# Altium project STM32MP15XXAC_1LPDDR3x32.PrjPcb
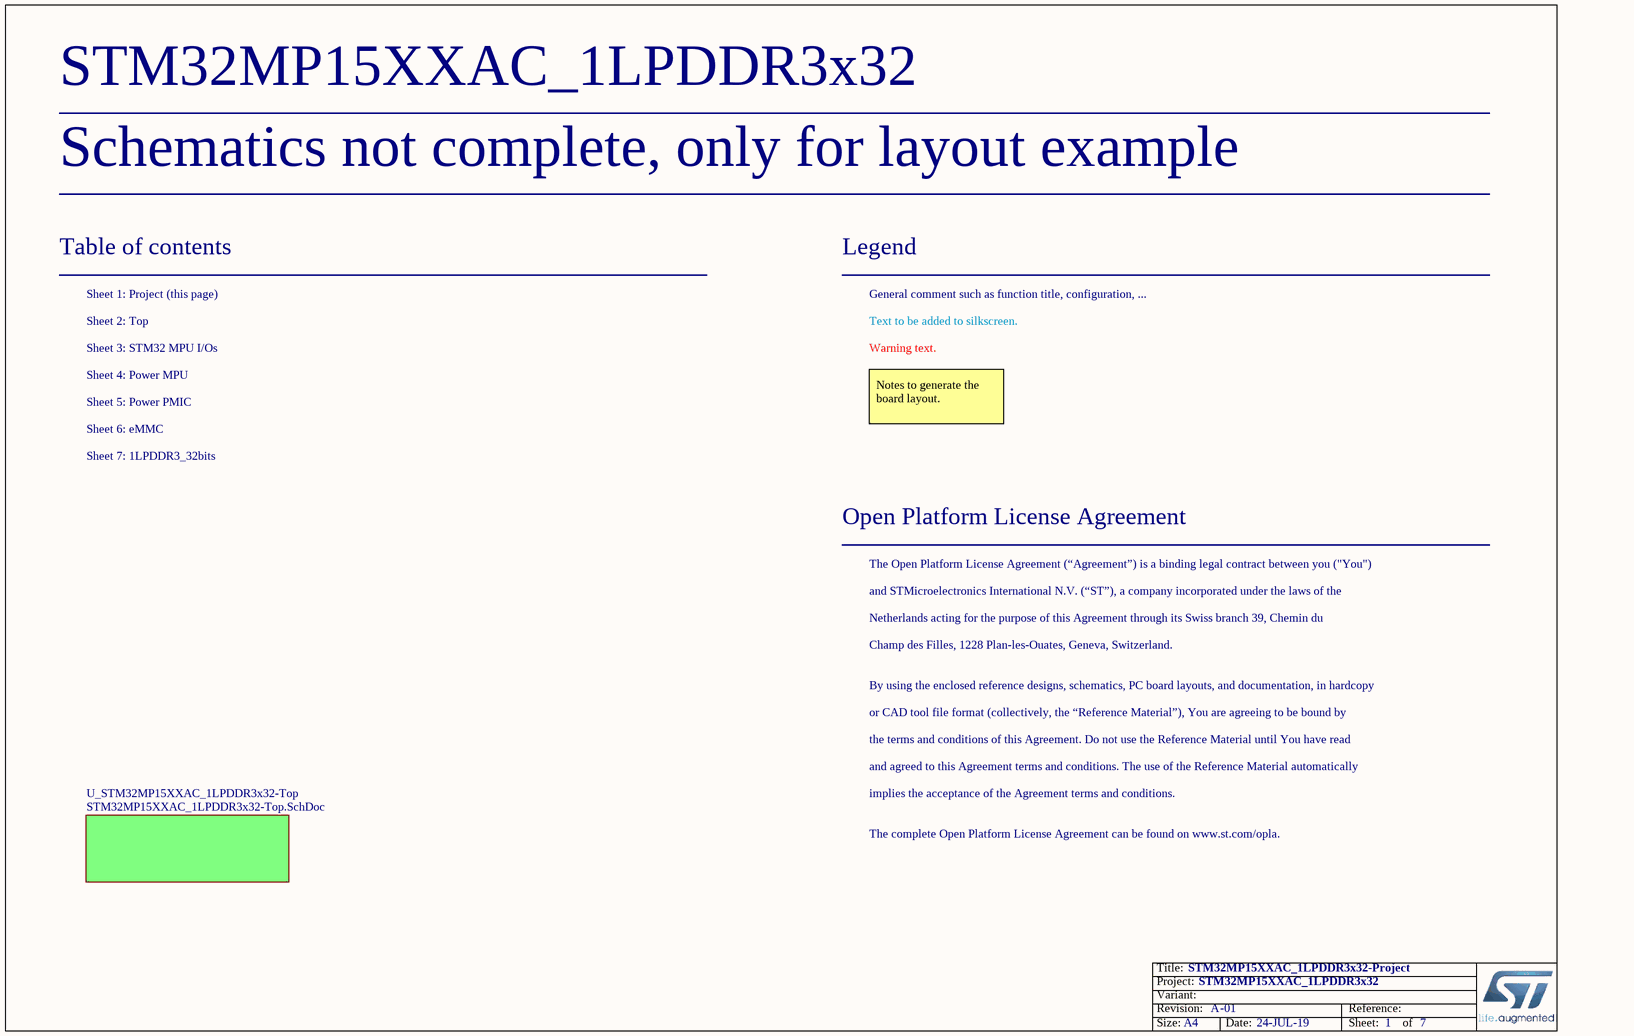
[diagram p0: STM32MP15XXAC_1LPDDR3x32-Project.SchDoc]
Board_Assembly_Revision: 01; Board_Document_Date: 24-JUL-19; Board_Name: STM32MP15XXAC_1LPDDR3x32; Board_PCB_Revision: A
7 sheets, 93 parts. Net scope: flat (ports and power ports of the same name join across sheets).
Board file: STM32MP15XXAC_1LPDDR3x32_A01.PcbDoc
Sheets:
  STM32MP15XXAC_1LPDDR3x32-Project.SchDoc
    U_STM32MP15XXAC_1LPDDR3x32-Top = STM32MP15XXAC_1LPDDR3x32-Top.SchDoc
      U_Power_PMIC = Power_PMIC.SchDoc
      U_Power_MPU = Power_MPU.SchDoc
      U_eMMC = eMMC.SchDoc
      U_STM32_MPU_IOs = STM32_MPU_IOs.SchDoc
      U_1LPDDR3_32bits = 1LPDDR3_32bits.SchDoc

## Sheet STM32MP15XXAC_1LPDDR3x32-Project.SchDoc: STM32MP15XXAC_1LPDDR3x32-Project
size A4; ApprovedBy: Not used; CheckedBy: Not used; Author: Not used; CompanyName: STMicroelectronics; DrawnBy: Not used; Engineer: Not used; Organization: Not used; Address1: Not used; Address2: Not used; Address3: Not used; Address4: Not used; DocumentNumber: Not used; Revision: Not used; SheetNumber: 1; SheetTotal: 7

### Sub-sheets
U_STM32MP15XXAC_1LPDDR3x32-Top = STM32MP15XXAC_1LPDDR3x32-Top.SchDoc: no entries

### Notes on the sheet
- Schematics not complete, only for layout example
- Table of contents
- Sheet 1: Project (this page)
- Legend
- General comment such as function title, configuration, ...
- Sheet 2: Top
- Sheet 3: STM32 MPU I/Os
- Sheet 4: Power MPU
- Text to be added to silkscreen.
- Warning text.
- Sheet 5: Power PMIC
- Sheet 6: eMMC
- Notes to generate the board layout.
- Sheet 7: 1LPDDR3_32bits
- Open Platform License Agreement
- The Open Platform License Agreement (“Agreement”) is a binding legal contract between you ("You")
- and STMicroelectronics International N.V. (“ST”), a company incorporated under the laws of the
- Netherlands acting for the purpose of this Agreement through its Swiss branch 39, Chemin du
- Champ des Filles, 1228 Plan-les-Ouates, Geneva, Switzerland.
- By using the enclosed reference designs, schematics, PC board layouts, and documentation, in hardcopy
- or CAD tool file format (collectively, the “Reference Material”), You are agreeing to be bound by
- the terms and conditions of this Agreement. Do not use the Reference Material until You have read
- and agreed to this Agreement terms and conditions. The use of the Reference Material automatically
- implies the acceptance of the Agreement terms and conditions.
- The complete Open Platform License Agreement can be found on www.st.com/opla.

## Sheet STM32MP15XXAC_1LPDDR3x32-Top.SchDoc: STM32MP15XXAC_1LPDDR3x32-TOP
size A4; Date: Not used; ApprovedBy: Not used; CheckedBy: Not used; Author: Not used; CompanyName: STMicroelectronics; DrawnBy: Not used; Engineer: Not used; Organization: Not used; Address1: Not used; Address2: Not used; Address3: Not used; Address4: Not used; DocumentNumber: Not used; Revision: Not used; SheetNumber: 2; SheetTotal: 7
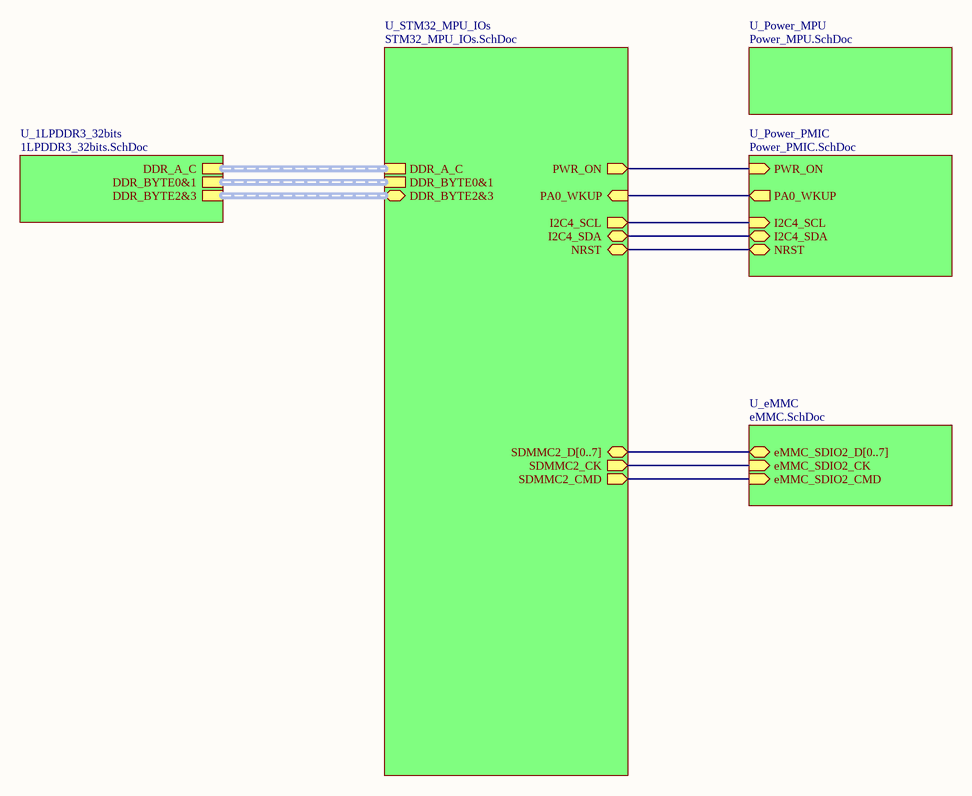
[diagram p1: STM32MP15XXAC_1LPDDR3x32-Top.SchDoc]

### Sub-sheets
U_1LPDDR3_32bits = 1LPDDR3_32bits.SchDoc: DDR_A_C (harness DDR_A_C), DDR_BYTE2&3 (harness DDR_BYTE_2&3), DDR_BYTE0&1 (harness DDR_BYTE_0&1)
U_eMMC = eMMC.SchDoc: eMMC_SDIO2_CK (in), eMMC_SDIO2_D[0..7] (bidir), eMMC_SDIO2_CMD (in)
U_Power_MPU = Power_MPU.SchDoc: no entries
U_Power_PMIC = Power_PMIC.SchDoc: I2C4_SDA (bidir), I2C4_SCL (in), PA0_WKUP (out), NRST (bidir), PWR_ON (in)
U_STM32_MPU_IOs = STM32_MPU_IOs.SchDoc: PA0_WKUP (in), NRST (bidir), PWR_ON (out), I2C4_SCL (out), I2C4_SDA (bidir), DDR_BYTE0&1 (harness DDR_BYTE_0&1), DDR_A_C (harness DDR_A_C), SDMMC2_D[0..7] (bidir), SDMMC2_CMD (out), SDMMC2_CK (out), DDR_BYTE2&3 (harness DDR_BYTE_2&3)

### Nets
(unnamed): sheet U_Power_PMIC/I2C4_SDA, sheet U_STM32_MPU_IOs/I2C4_SDA
(unnamed): sheet U_Power_PMIC/I2C4_SCL, sheet U_STM32_MPU_IOs/I2C4_SCL  [a separate net that carries the same name]
(unnamed): sheet U_Power_PMIC/PA0_WKUP, sheet U_STM32_MPU_IOs/PA0_WKUP  [a separate net that carries the same name]
(unnamed): sheet U_Power_PMIC/NRST, sheet U_STM32_MPU_IOs/NRST  [a separate net that carries the same name]
(unnamed): sheet U_Power_PMIC/PWR_ON, sheet U_STM32_MPU_IOs/PWR_ON  [a separate net that carries the same name]
(unnamed): sheet U_eMMC/eMMC_SDIO2_CK, sheet U_STM32_MPU_IOs/SDMMC2_CK  [a separate net that carries the same name]
(unnamed): sheet U_eMMC/eMMC_SDIO2_CMD, sheet U_STM32_MPU_IOs/SDMMC2_CMD  [a separate net that carries the same name]

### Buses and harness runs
bus sheet U_eMMC/eMMC_SDIO2_D[0..7] = sheet U_STM32_MPU_IOs/SDMMC2_D[0..7]
harness sheet U_1LPDDR3_32bits/DDR_A_C = sheet U_STM32_MPU_IOs/DDR_A_C
harness sheet U_1LPDDR3_32bits/DDR_BYTE0&1 = sheet U_STM32_MPU_IOs/DDR_BYTE0&1
harness sheet U_1LPDDR3_32bits/DDR_BYTE2&3 = sheet U_STM32_MPU_IOs/DDR_BYTE2&3

## Sheet Power_PMIC.SchDoc: Power_PMIC
size A3; CompanyName: STMicroelectronics; Organization: Microcontrollers Division; Address1: 12, Rue Jules HOROWITZ; Address2: 38019 Grenoble; Address3: FRANCE; SheetNumber: 5; SheetTotal: 7
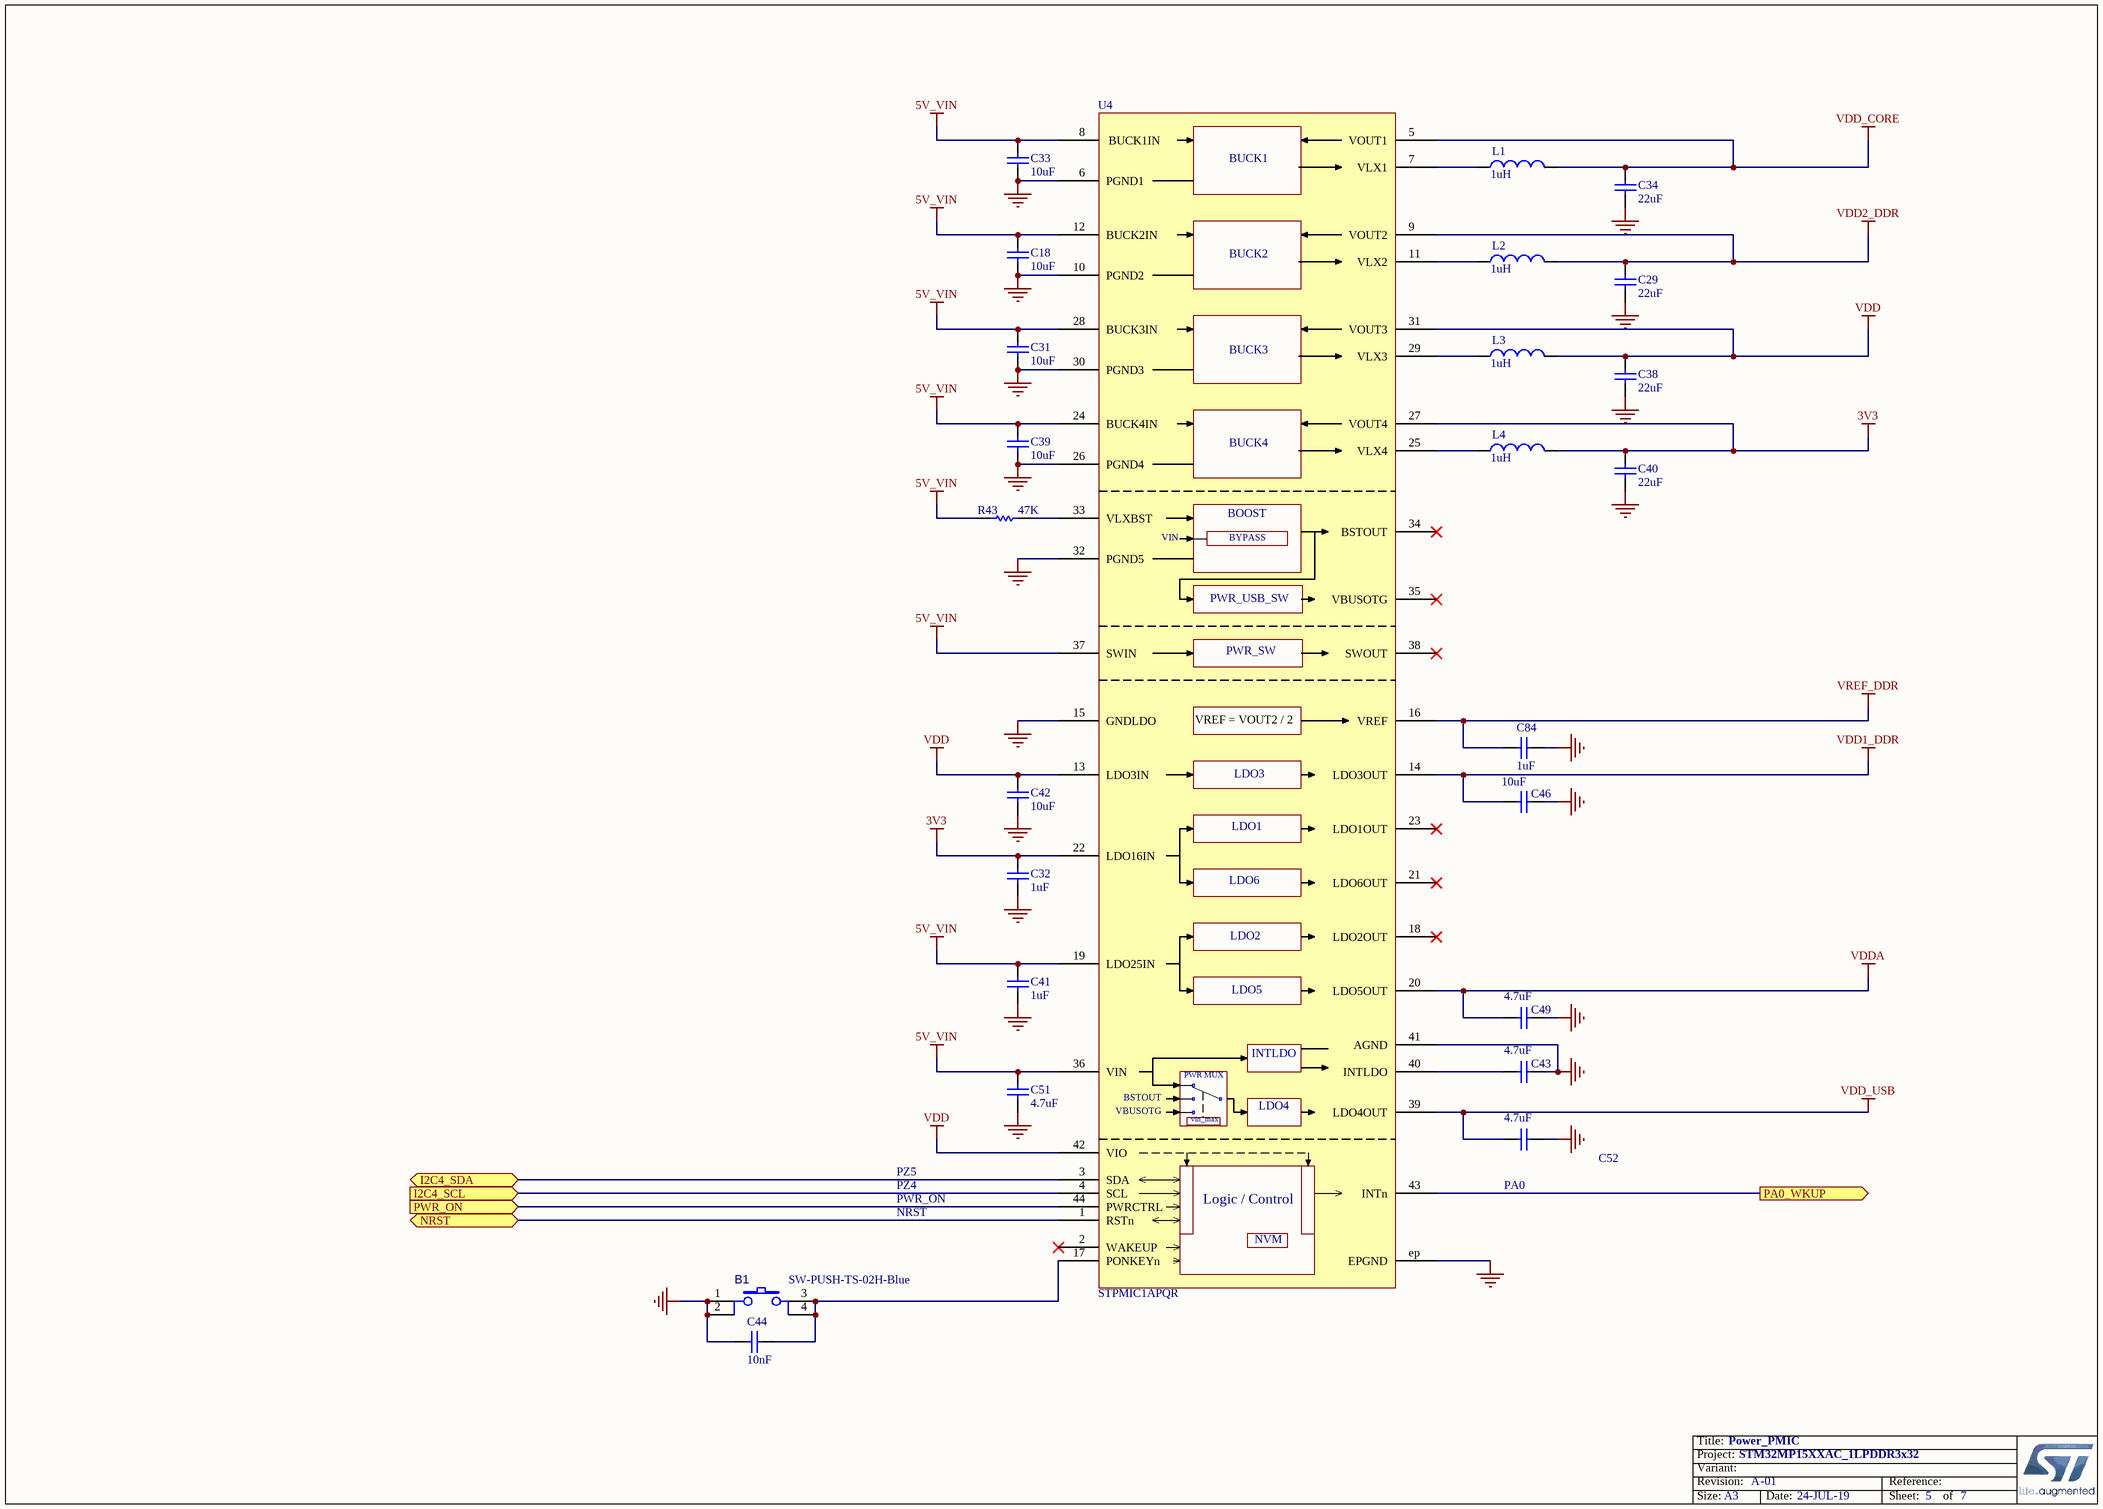
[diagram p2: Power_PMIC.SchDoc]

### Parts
B1  SW-PUSH-TS-02H-Blue  [SWI_JIUBABA_C-TS-02H-2-5-B-V-T_R_BLUE]
C18  value 10uF  [C0603]  (hidden comment: Capacitor)
C29  value 22uF  [C0603]  (hidden comment: Capacitor)
C31  value 10uF  [C0603]  (hidden comment: Capacitor)
C32  value 1uF  [C0402]  (hidden comment: Capacitor)
C33  value 10uF  [C0603]  (hidden comment: Capacitor)
C34  value 22uF  [C0603]  (hidden comment: Capacitor)
C38  value 22uF  [C0603]  (hidden comment: Capacitor)
C39  value 10uF  [C0603]  (hidden comment: Capacitor)
C40  value 22uF  [C0603]  (hidden comment: Capacitor)
C41  value 1uF  [C0402]  (hidden comment: Capacitor)
C42  value 10uF  [C0603]  (hidden comment: Capacitor)
C43  value 4.7uF  [C0402]  (hidden comment: Capacitor)
C44  value 10nF  [C0402]  (hidden comment: Capacitor)
C46  value 10uF  [C0603]  (hidden comment: Capacitor)
C49  value 4.7uF  [C0402]  (hidden comment: Capacitor)
C51  value 4.7uF  [C0402]  (hidden comment: Capacitor)
C52  value 4.7uF  [C0402]  (hidden comment: Capacitor)
C84  value 1uF  [C0402]  (hidden comment: Capacitor)
L1  value 1uH  [IND_2520_TOKO_DFE252012P]  (hidden comment: IND_1uH_42mohm_3.2A)
L2  value 1uH  [IND_2520_TOKO_DFE252012P]  (hidden comment: IND_1uH_42mohm_3.2A)
L3  value 1uH  [IND_2520_TOKO_DFE252012P]  (hidden comment: IND_1uH_42mohm_3.2A)
L4  value 1uH  [IND_2520_TOKO_DFE252012P]  (hidden comment: IND_1uH_42mohm_3.2A)
R43  value 47K  [R0402]  (hidden comment: Resistor)
U4  value STPMIC1APQR  [ICC_WFQFN44-EPAD_5X6_P040]  (hidden comment: STPMU1)

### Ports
I2C4_SCL (in), I2C4_SDA (bidir), NRST (bidir), PA0_WKUP (out), PWR_ON (in)

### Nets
3V3: C32.2 C40.2 L4.2 U4.22(LDO16IN) U4.27(VOUT4)
5V_VIN: C18.2 C31.2 C33.2 C39.2 C41.2 C51.2 R43.2 U4.8(BUCK1IN) U4.12(BUCK2IN) U4.19(LDO25IN) U4.24(BUCK4IN) U4.28(BUCK3IN) U4.36(VIN) U4.37(SWIN)
GND: B1.1 B1.2 C18.1 C29.1 C31.1 C32.1 C33.1 C34.1 C38.1 C39.1 C40.1 C41.1 C42.1 C43.2 C44.1 C46.1 C49.1 C51.1 C52.1 C84.1 U4.6(PGND1) U4.10(PGND2) U4.15(GNDLDO) U4.26(PGND4) U4.30(PGND3) U4.32(PGND5) U4.41(AGND) U4.ep(EPGND)
VDD: C38.2 C42.2 L3.2 U4.13(LDO3IN) U4.31(VOUT3) U4.42(VIO)
VDD1_DDR: C46.2 U4.14(LDO3OUT)
VDD2_DDR: C29.2 L2.2 U4.9(VOUT2)
VDD_CORE: C34.2 L1.2 U4.5(VOUT1)
VDD_USB: C52.2 U4.39(LDO4OUT)
VDDA: C49.2 U4.20(LDO5OUT)
VREF_DDR: C84.2 U4.16(VREF)
I2C4_SCL: U4.4(SCL) ; port I2C4_SCL
I2C4_SDA: U4.3(SDA) ; port I2C4_SDA
NRST: U4.1(RSTn) ; port NRST
PA0_WKUP: U4.43(INTn) ; port PA0_WKUP
PWR_ON: U4.44(PWRCTRL) ; port PWR_ON
NetB1_3: B1.3 B1.4 C44.2 U4.17(PONKEYn)
NetC43_1: C43.1 U4.40(INTLDO)
NetL1_1: L1.1 U4.7(VLX1)
NetL2_1: L2.1 U4.11(VLX2)
NetL3_1: L3.1 U4.29(VLX3)
NetL4_1: L4.1 U4.25(VLX4)
NetR43_1: R43.1 U4.33(VLXBST)

Not connected (* = marked no-connect by the designer): U4 2(WAKEUP)* 18(LDO2OUT)* 21(LDO6OUT)* 23(LDO1OUT)* 34(BSTOUT)* 35(VBUSOTG)* 38(SWOUT)*

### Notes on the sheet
- PZ5
- PZ4
- (near C52) PA0
- NRST
- PWR_ON

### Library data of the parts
B1 = MCD-00172: Switch HW SMD blue; Part_Type: Misc; Manufacturer_Part_Number: C-TS-02H-2.5-B-V-T/R BLUE; Manufacturer: JIUBABA; Provided_By: SUBCO
C18 C31 C33 C39 C42 = MCD-00099: Capacitor, MLCC, 10uF, 10V, X5R, +/-10%, 0603, T=0,8mm; Manufacturer_Part_Number: GRM188R61A106KE69D; Manufacturer: MURATA; Provided_By: SUBCO; ECCN_US: EAR99; ECCN_EU: NEC; Order_Code_RS: 170-6168
C29 C34 C38 C40 = MCD-00100: Capacitor, MLCC, 22uF, 6V3, X5R, +/-20%, 0603, T=0,8mm; Manufacturer_Part_Number: GRM188R60J226MEA0J; Manufacturer: MURATA; Provided_By: SUBCO; ECCN_US: EAR99; ECCN_EU: NEC
C32 C41 C84 = MCD-00095: Capacitor, MLCC, 1uF, 25V, X5R, +/-10%, 0402, T=0,5mm; Manufacturer_Part_Number: GRM155R61E105KA12; Manufacturer: MURATA; Alternate_Manufacturer_Part_Number: GRM155R60J105KE19; Provided_By: SUBCO; ECCN_US: EAR99; ECCN_EU: NEC; Order_Code_RS: 846-7287
C43 C49 C51 C52 = MCD-01356: Capacitor, MLCC, 4.7uF, 6V3, X5R, +/-20%, 0402, T=0,5mm; Manufacturer_Part_Number: GRM155R60J475ME47; Manufacturer: MURATA; Alternate_Manufacturer_Part_Number: GRM155R60J475ME87; ECCN_US: EAR99; ECCN_EU: NEC; Provided_By: SUBCO; Order_Code_RS: 814-5230
C44 = MCD-00011: Capacitor, MLCC, 10nF, 16V, X7R, +/-10%, 0402, T=0.5mm; Manufacturer_Part_Number: CC0402KRX7R7BB103; Manufacturer: YAGEO; Provided_By: SUBCO; ECCN_US: EAR99; ECCN_EU: NEC; Order_Code_RS: 669-8688
C46 = MCD-00099: Capacitor, MLCC, 10uF, 10V, X5R, +/-10%, 0603, T=0,8mm; Manufacturer_Part_Number: GRM188R61A106KE69D; Manufacturer: MURATA; ECCN_US: EAR99; ECCN_EU: NEC; Provided_By: SUBCO; Order_Code_RS: 170-6168
L1-L4 = MCD-01122: Power Inductor ,1uH,4.3A max,+/-20%,0.042ohm,2520; Manufacturer_Part_Number: DFE252012P-1ROM=P2; Manufacturer: MURATA; Provided_By: SUBCO; ECCN_US: EAR99; ECCN_EU: NEC
R43 = MCD-00063: Resistor,47K,0402,1%,1/16W; Manufacturer_Part_Number: RC0402FR-0747KL; Manufacturer: YAGEO; Provided_By: SUBCO; ECCN_US: EAR99; ECCN_EU: NEC
U4 = MCD-01650: ST PMIC:  4 step-down + 1 advanced boost SMPS, 6 LDOs, 2 pwr switches, DDR Vref, NVM option 'A' for IO@3.3V; Part_Type: IC; Manufacturer: STMICROELECTRONICS; BMS_Part_Number: 9177723; ECCN_US: EAR99; ECCN_EU: NEC; Provided_By: SUBCO with ST control; Company_Nationality: Netherlands

## Sheet Power_MPU.SchDoc: Power_MPU
size A3; CompanyName: STMicroelectronics; SheetNumber: 4; SheetTotal: 7
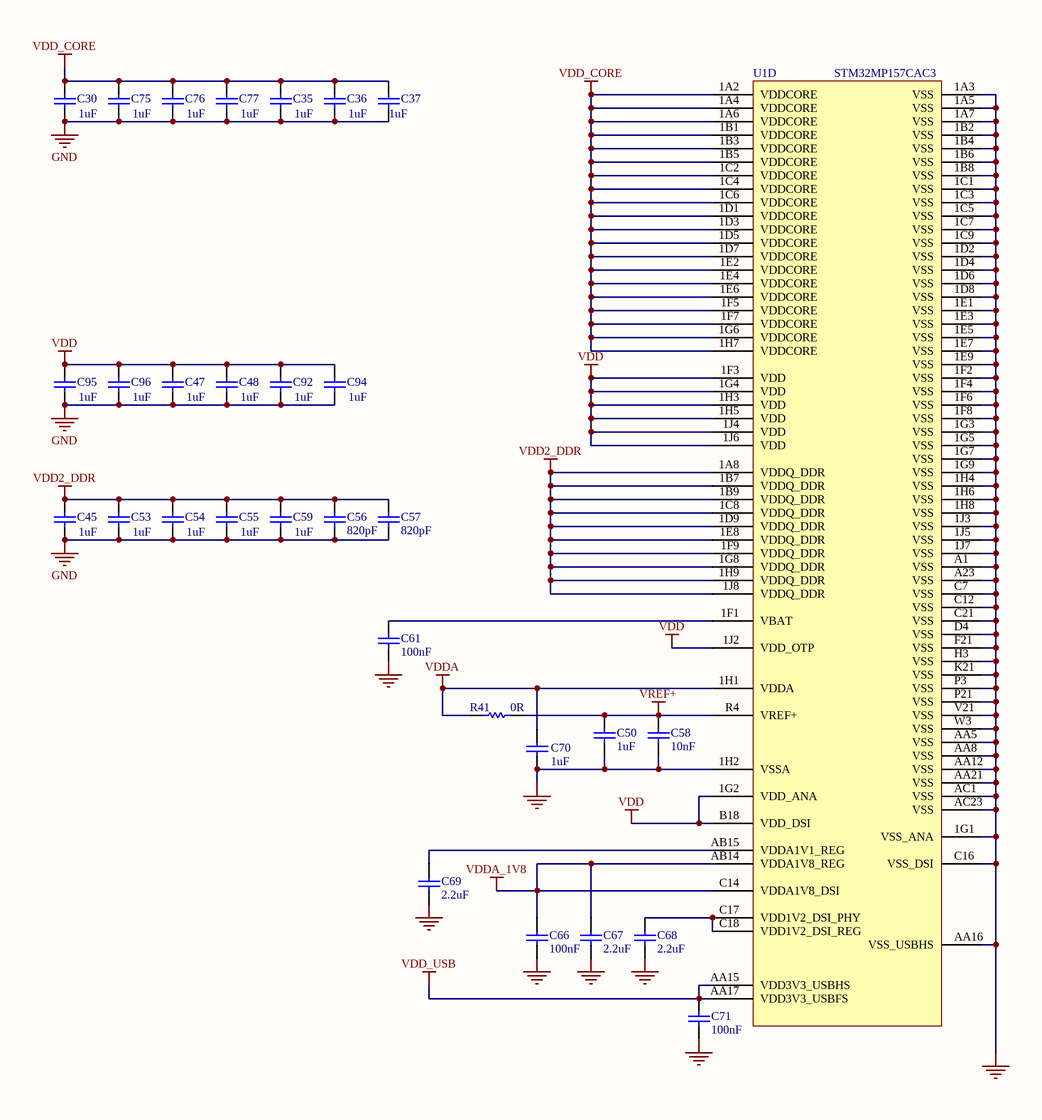
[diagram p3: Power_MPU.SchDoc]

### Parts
C30  value 1uF  [C0402]  (hidden comment: Capacitor)
C35  value 1uF  [C0402]  (hidden comment: Capacitor)
C36  value 1uF  [C0402]  (hidden comment: Capacitor)
C37  value 1uF  [C0402]  (hidden comment: Capacitor)
C45  value 1uF  [C0402]  (hidden comment: Capacitor)
C47  value 1uF  [C0402]  (hidden comment: Capacitor)
C48  value 1uF  [C0402]  (hidden comment: Capacitor)
C50  value 1uF  [C0402]  (hidden comment: Capacitor)
C53  value 1uF  [C0402]  (hidden comment: Capacitor)
C54  value 1uF  [C0402]  (hidden comment: Capacitor)
C55  value 1uF  [C0402]  (hidden comment: Capacitor)
C56  value 820pF  [C0402]  (hidden comment: Capacitor)
C57  value 820pF  [C0402]  (hidden comment: Capacitor)
C58  value 10nF  [C0402]  (hidden comment: Capacitor)
C59  value 1uF  [C0402]  (hidden comment: Capacitor)
C61  value 100nF  [C0402]  (hidden comment: Capacitor)
C66  value 100nF  [C0402]  (hidden comment: Capacitor)
C67  value 2.2uF  [C0402]  (hidden comment: Capacitor)
C68  value 2.2uF  [C0402]  (hidden comment: Capacitor)
C69  value 2.2uF  [C0402]  (hidden comment: Capacitor)
C70  value 1uF  [C0402]  (hidden comment: Capacitor)
C71  value 100nF  [C0402]  (hidden comment: Capacitor)
C75  value 1uF  [C0402]  (hidden comment: Capacitor)
C76  value 1uF  [C0402]  (hidden comment: Capacitor)
C77  value 1uF  [C0402]  (hidden comment: Capacitor)
C92  value 1uF  [C0402]  (hidden comment: Capacitor)
C94  value 1uF  [C0402]  (hidden comment: Capacitor)
C95  value 1uF  [C0402]  (hidden comment: Capacitor)
C96  value 1uF  [C0402]  (hidden comment: Capacitor)
R41  value 0R  [R0402]  (hidden comment: Resistor)
U1  STM32MP157CAC3  [ICC_TFBGA361_12X12_STM32MP157CAC3_P050-065]  (part D of 5)

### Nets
GND: C30.1 C35.1 C36.1 C37.1 C45.1 C47.1 C48.1 C50.1 C53.1 C54.1 C55.1 C56.1 C57.1 C58.1 C59.1 C61.1 C66.1 C67.1 C68.1 C69.1 C70.1 C71.1 C75.1 C76.1 C77.1 C92.1 C94.1 C95.1 C96.1 U1.1A3(VSS) U1.1A5(VSS) U1.1A7(VSS) U1.1B2(VSS) U1.1B4(VSS) U1.1B6(VSS) U1.1B8(VSS) U1.1C1(VSS) U1.1C3(VSS) U1.1C5(VSS) U1.1C7(VSS) U1.1C9(VSS) U1.1D2(VSS) U1.1D4(VSS) U1.1D6(VSS) U1.1D8(VSS) U1.1E1(VSS) U1.1E3(VSS) U1.1E5(VSS) U1.1E7(VSS) U1.1E9(VSS) U1.1F2(VSS) U1.1F4(VSS) U1.1F6(VSS) U1.1F8(VSS) U1.1G1(VSS_ANA) U1.1G3(VSS) U1.1G5(VSS) U1.1G7(VSS) U1.1G9(VSS) U1.1H2(VSSA) U1.1H4(VSS) U1.1H6(VSS) U1.1H8(VSS) U1.1J3(VSS) U1.1J5(VSS) U1.1J7(VSS) U1.A1(VSS) U1.A23(VSS) U1.AA5(VSS) U1.AA8(VSS) U1.AA12(VSS) U1.AA16(VSS_USBHS) U1.AA21(VSS) U1.AC1(VSS) U1.AC23(VSS) U1.C7(VSS) U1.C12(VSS) U1.C16(VSS_DSI) U1.C21(VSS) U1.D4(VSS) U1.F21(VSS) U1.H3(VSS) U1.K21(VSS) U1.P3(VSS) U1.P21(VSS) U1.V21(VSS) U1.W3(VSS)
VDD: C47.2 C48.2 C92.2 C94.2 C95.2 C96.2 U1.1F3(VDD) U1.1G2(VDD_ANA) U1.1G4(VDD) U1.1H3(VDD) U1.1H5(VDD) U1.1J2(VDD_OTP) U1.1J4(VDD) U1.1J6(VDD) U1.B18(VDD_DSI)
VDD2_DDR: C45.2 C53.2 C54.2 C55.2 C56.2 C57.2 C59.2 U1.1A8(VDDQ_DDR) U1.1B7(VDDQ_DDR) U1.1B9(VDDQ_DDR) U1.1C8(VDDQ_DDR) U1.1D9(VDDQ_DDR) U1.1E8(VDDQ_DDR) U1.1F9(VDDQ_DDR) U1.1G8(VDDQ_DDR) U1.1H9(VDDQ_DDR) U1.1J8(VDDQ_DDR)
VDD_CORE: C30.2 C35.2 C36.2 C37.2 C75.2 C76.2 C77.2 U1.1A2(VDDCORE) U1.1A4(VDDCORE) U1.1A6(VDDCORE) U1.1B1(VDDCORE) U1.1B3(VDDCORE) U1.1B5(VDDCORE) U1.1C2(VDDCORE) U1.1C4(VDDCORE) U1.1C6(VDDCORE) U1.1D1(VDDCORE) U1.1D3(VDDCORE) U1.1D5(VDDCORE) U1.1D7(VDDCORE) U1.1E2(VDDCORE) U1.1E4(VDDCORE) U1.1E6(VDDCORE) U1.1F5(VDDCORE) U1.1F7(VDDCORE) U1.1G6(VDDCORE) U1.1H7(VDDCORE)
VDD_USB: C71.2 U1.AA15(VDD3V3_USBHS) U1.AA17(VDD3V3_USBFS)
VDDA: C70.2 R41.1 U1.1H1(VDDA)
VDDA_1V8: C66.2 C67.2 U1.AB14(VDDA1V8_REG) U1.C14(VDDA1V8_DSI)
VREF+: C50.2 C58.2 R41.2 U1.R4(VREF+)
NetC61_2: C61.2 U1.1F1(VBAT)
NetC68_2: C68.2 U1.C17(VDD1V2_DSI_PHY) U1.C18(VDD1V2_DSI_REG)
NetC69_2: C69.2 U1.AB15(VDDA1V1_REG)

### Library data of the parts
C30 C35-C37 C45 C47 C48 C50 C53-C55 C59 C70 C75-C77 C92 C94-C96 = MCD-00095: Capacitor, MLCC, 1uF, 25V, X5R, +/-10%, 0402, T=0,5mm; Manufacturer_Part_Number: GRM155R61E105KA12; Manufacturer: MURATA; Alternate_Manufacturer_Part_Number: GRM155R60J105KE19; ECCN_US: EAR99; ECCN_EU: NEC; Provided_By: SUBCO; Order_Code_RS: 846-7287
C56 C57 = MCD-01508: Capacitor, MLCC, 820pF, 50V, X7R, +/-10%, 0402, T=0.55mm; Manufacturer_Part_Number: CC0402KRX7R9BB821; Manufacturer: YAGEO; ECCN_US: EAR99; ECCN_EU: NEC; Provided_By: SUBCO; Order_Code_RS: 669-8754
C58 = MCD-00011: Capacitor, MLCC, 10nF, 16V, X7R, +/-10%, 0402, T=0.5mm; Manufacturer_Part_Number: CC0402KRX7R7BB103; Manufacturer: YAGEO; ECCN_US: EAR99; ECCN_EU: NEC; Provided_By: SUBCO; Order_Code_RS: 669-8688
C61 C66 C71 = MCD-00006: Capacitor, MLCC, 100nF, 16V, X7R, +/-10%, 0402, T=0.5mm; Manufacturer_Part_Number: CC0402KRX7R7BB104; Manufacturer: YAGEO; Alternate_Manufacturer_Part_Number: GCM155R71C104KA55D; Alternate_Manufacturer: MURATA; ECCN_US: EAR99; ECCN_EU: NEC; Provided_By: SUBCO; Order_Code_RS: 616-9701
C67-C69 = MCD-01823: Capacitor,MLCC, 2.2uF, 6V3, X5R,+/-10%, 0402, T=0.5mm; Manufacturer_Part_Number: GRM155R60J225KE95D; Manufacturer: MURATA; ECCN_US: EAR99; ECCN_EU: NEC; Provided_By: SUBCO; Order_Code_RS: 172-6478
R41 = MCD-00052: Resistor,0R,0402,5%,1/16W; Manufacturer_Part_Number: RC0402JR-070RL; Manufacturer: YAGEO; ECCN_US: EAR99; ECCN_EU: NEC; Provided_By: SUBCO; Order_Code_RS: 618-5804
U1 = MCD-00677: MPU TFBGA12x12 secure boot+crypto; Part_Type: IC; Manufacturer: STMICROELECTRONICS; BMS_Part_Number: 9175503; ECCN_US: 5A002A4; ECCN_EU: NEC; Provided_By: SUBCO with ST control; Company_Nationality: Netherlands

## Sheet eMMC.SchDoc: eMMC
size A3; CompanyName: STMicroelectronics; Address1: 12, Rue Jules HOROWITZ; Address2: 38019 Grenoble; Address3: FRANCE; SheetNumber: 6; SheetTotal: 7
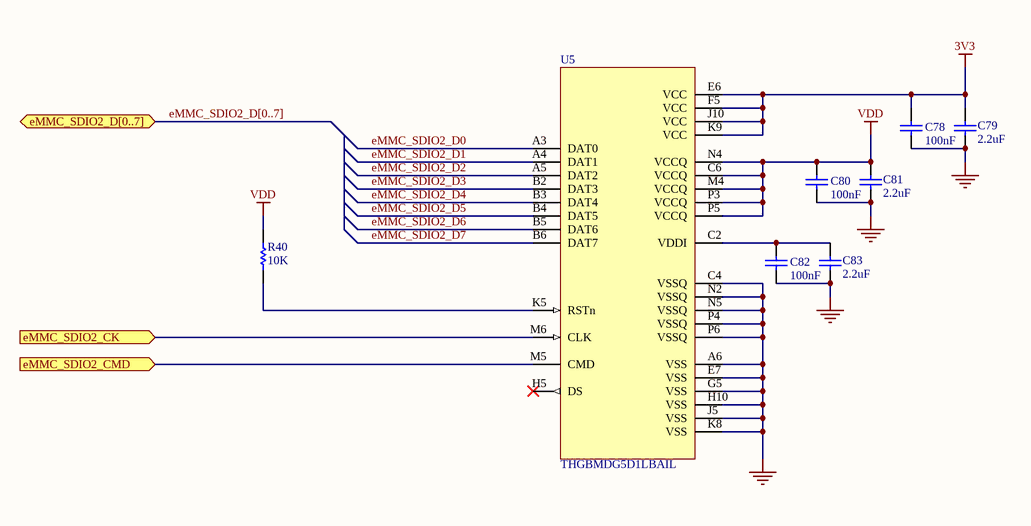
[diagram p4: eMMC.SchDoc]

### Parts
C78  value 100nF  [C0402]  (hidden comment: Capacitor)
C79  value 2.2uF  [C0603]  (hidden comment: Capacitor)
C80  value 100nF  [C0402]  (hidden comment: Capacitor)
C81  value 2.2uF  [C0603]  (hidden comment: Capacitor)
C82  value 100nF  [C0402]  (hidden comment: Capacitor)
C83  value 2.2uF  [C0603]  (hidden comment: Capacitor)
R40  value 10K  [R0402]  (hidden comment: Resistor)
U5  value THGBMDG5D1LBAIL  [ICC_P-WFBGA153_13X11P5_P050]  (hidden comment: eMMC_THGBMDG5D1LBAIL)

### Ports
eMMC_SDIO2_CK (in), eMMC_SDIO2_CMD (in), eMMC_SDIO2_D[0..7] (bidir)

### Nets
3V3: C78.2 C79.2 U5.E6(VCC) U5.F5(VCC) U5.J10(VCC) U5.K9(VCC)
GND: C78.1 C79.1 C80.1 C81.1 C82.1 C83.1 U5.A6(VSS) U5.C4(VSSQ) U5.E7(VSS) U5.G5(VSS) U5.H10(VSS) U5.J5(VSS) U5.K8(VSS) U5.N2(VSSQ) U5.N5(VSSQ) U5.P4(VSSQ) U5.P6(VSSQ)
VDD: C80.2 C81.2 R40.2 U5.C6(VCCQ) U5.M4(VCCQ) U5.N4(VCCQ) U5.P3(VCCQ) U5.P5(VCCQ)
eMMC_SDIO2_CK: U5.M6(CLK) ; port eMMC_SDIO2_CK
eMMC_SDIO2_CMD: U5.M5(CMD) ; port eMMC_SDIO2_CMD
eMMC_SDIO2_D0: U5.A3(DAT0)
eMMC_SDIO2_D1: U5.A4(DAT1)
eMMC_SDIO2_D2: U5.A5(DAT2)
eMMC_SDIO2_D3: U5.B2(DAT3)
eMMC_SDIO2_D4: U5.B3(DAT4)
eMMC_SDIO2_D5: U5.B4(DAT5)
eMMC_SDIO2_D6: U5.B5(DAT6)
eMMC_SDIO2_D7: U5.B6(DAT7)
NetC82_2: C82.2 C83.2 U5.C2(VDDI)
NetR40_1: R40.1 U5.K5(RSTn)

Not connected (* = marked no-connect by the designer): U5 H5(DS)*

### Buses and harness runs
bus eMMC_SDIO2_D[0..7] = port eMMC_SDIO2_D[0..7]

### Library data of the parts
C78 C80 C82 = MCD-00006: Capacitor, MLCC, 100nF, 16V, X7R, +/-10%, 0402, T=0.5mm; Manufacturer_Part_Number: CC0402KRX7R7BB104; Manufacturer: YAGEO; Alternate_Manufacturer_Part_Number: GCM155R71C104KA55D; Alternate_Manufacturer: MURATA; Provided_By: SUBCO; ECCN_US: EAR99; ECCN_EU: NEC; Order_Code_RS: 616-9701
C79 C81 C83 = MCD-00012: Capacitor, MLCC, 2.2uF, 10V, X5R, +/- 10%, 0603, T=0,8mm; Manufacturer_Part_Number: CC0603KRX5R6BB225; Manufacturer: YAGEO; Alternate_Manufacturer_Part_Number: C0603C225K8PACTU; Alternate_Manufacturer: KEMET; BMS_Part_Number: 9142010; Provided_By: SUBCO; ECCN_US: EAR99; ECCN_EU: NEC
R40 = MCD-00053: Resistor,10K,0402,1%,1/16W; Manufacturer_Part_Number: RC0402FR-0710KL; Manufacturer: YAGEO; BMS_Part_Number: 9131590; Provided_By: SUBCO; ECCN_US: EAR99; ECCN_EU: NEC
U5 = MCD-00110: Memory,e-MMC,4GB,3V3,WFBGA,153pins; Part_Type: IC; Manufacturer: TOSHIBA; BMS_Part_Number: 9171005; Provided_By: SUBCO; ECCN_US: 3A991; ECCN_EU: NEC

## Sheet STM32_MPU_IOs.SchDoc: MPU
size A3; SheetNumber: 3; SheetTotal: 7
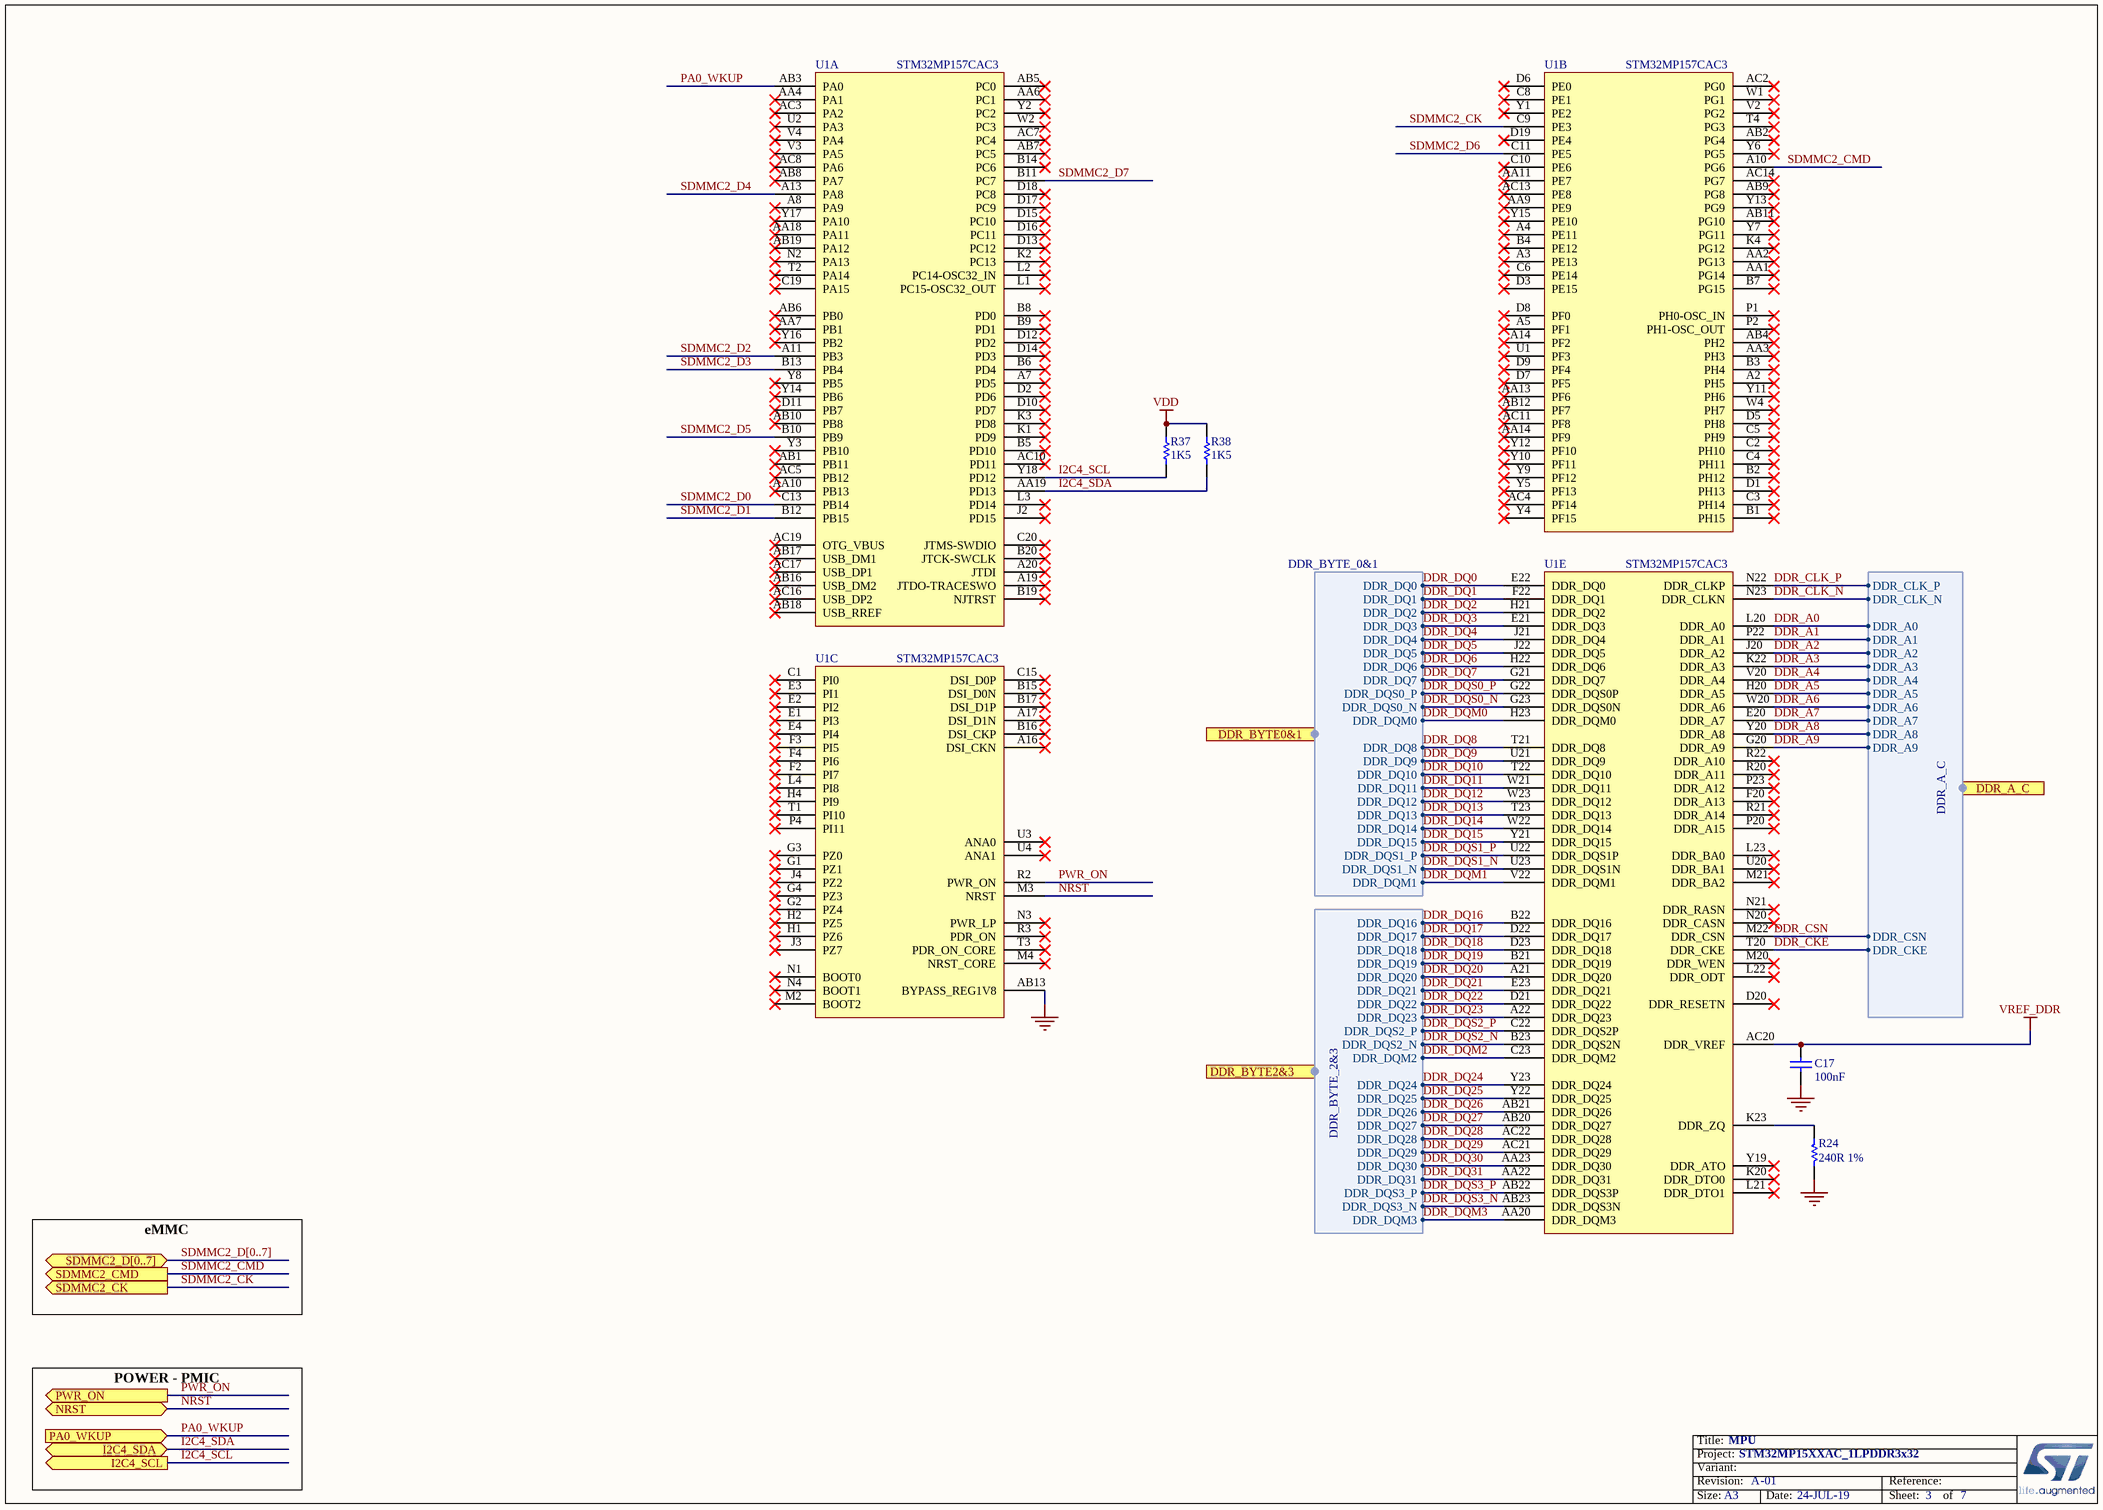
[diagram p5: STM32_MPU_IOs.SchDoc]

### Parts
C17  value 100nF  [C0402]  (hidden comment: Capacitor)
R24  value 240R 1%  [R0402]  (hidden comment: Resistor)
R37  value 1K5  [R0402]  (hidden comment: Resistor)
R38  value 1K5  [R0402]  (hidden comment: Resistor)
U1  STM32MP157CAC3  [ICC_TFBGA361_12X12_STM32MP157CAC3_P050-065]  (parts A,B,C,E of 5)

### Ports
DDR_A_C (harness DDR_A_C), DDR_BYTE0&1 (harness DDR_BYTE_0&1), DDR_BYTE2&3 (harness DDR_BYTE_2&3), I2C4_SCL (out), I2C4_SDA (bidir), NRST (bidir), PA0_WKUP (in), PWR_ON (out), SDMMC2_CK (out), SDMMC2_CMD (out), SDMMC2_D[0..7] (bidir)

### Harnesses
DDR_BYTE_0&1: DDR_DQ0, DDR_DQ1, DDR_DQ2, DDR_DQ3, DDR_DQ4, DDR_DQ5, DDR_DQ6, DDR_DQ7, DDR_DQS0_P, DDR_DQS0_N, DDR_DQM0, DDR_DQ8, DDR_DQ9, DDR_DQ10, DDR_DQ11, DDR_DQ12, DDR_DQ13, DDR_DQ14, DDR_DQ15, DDR_DQS1_P, DDR_DQS1_N, DDR_DQM1
DDR_BYTE_2&3: DDR_DQ20, DDR_DQ16, DDR_DQ18, DDR_DQ17, DDR_DQ22, DDR_DQ19, DDR_DQ21, DDR_DQ23, DDR_DQS2_P, DDR_DQS2_N, DDR_DQ26, DDR_DQM2, DDR_DQ24, DDR_DQ28, DDR_DQ25, DDR_DQ27, DDR_DQ29, DDR_DQ30, DDR_DQ31, DDR_DQS3_P, DDR_DQS3_N, DDR_DQM3
DDR_A_C: DDR_CLK_P, DDR_CLK_N, DDR_A0, DDR_A1, DDR_A2, DDR_A3, DDR_A4, DDR_A5, DDR_A6, DDR_A7, DDR_A8, DDR_A9, DDR_CSN, DDR_CKE

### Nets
GND: C17.2 R24.2 U1.AB13(BYPASS_REG1V8)
VDD: R37.1 R38.1
VREF_DDR: C17.1 U1.AC20(DDR_VREF)
DDR_A0: U1.L20(DDR_A0) ; port DDR_A_C.DDR_A0
DDR_A1: U1.P22(DDR_A1) ; port DDR_A_C.DDR_A1
DDR_A2: U1.J20(DDR_A2) ; port DDR_A_C.DDR_A2
DDR_A3: U1.K22(DDR_A3) ; port DDR_A_C.DDR_A3
DDR_A4: U1.V20(DDR_A4) ; port DDR_A_C.DDR_A4
DDR_A5: U1.H20(DDR_A5) ; port DDR_A_C.DDR_A5
DDR_A6: U1.W20(DDR_A6) ; port DDR_A_C.DDR_A6
DDR_A7: U1.E20(DDR_A7) ; port DDR_A_C.DDR_A7
DDR_A8: U1.Y20(DDR_A8) ; port DDR_A_C.DDR_A8
DDR_A9: U1.G20(DDR_A9) ; port DDR_A_C.DDR_A9
DDR_CKE: U1.T20(DDR_CKE) ; port DDR_A_C.DDR_CKE
DDR_CLK_N: U1.N23(DDR_CLKN) ; port DDR_A_C.DDR_CLK_N
DDR_CLK_P: U1.N22(DDR_CLKP) ; port DDR_A_C.DDR_CLK_P
DDR_CSN: U1.M22(DDR_CSN) ; port DDR_A_C.DDR_CSN
DDR_DQ0: U1.E22(DDR_DQ0) ; port DDR_BYTE0&1.DDR_DQ0
DDR_DQ1: U1.F22(DDR_DQ1) ; port DDR_BYTE0&1.DDR_DQ1
DDR_DQ2: U1.H21(DDR_DQ2) ; port DDR_BYTE0&1.DDR_DQ2
DDR_DQ3: U1.E21(DDR_DQ3) ; port DDR_BYTE0&1.DDR_DQ3
DDR_DQ4: U1.J21(DDR_DQ4) ; port DDR_BYTE0&1.DDR_DQ4
DDR_DQ5: U1.J22(DDR_DQ5) ; port DDR_BYTE0&1.DDR_DQ5
DDR_DQ6: U1.H22(DDR_DQ6) ; port DDR_BYTE0&1.DDR_DQ6
DDR_DQ7: U1.G21(DDR_DQ7) ; port DDR_BYTE0&1.DDR_DQ7
DDR_DQ8: U1.T21(DDR_DQ8) ; port DDR_BYTE0&1.DDR_DQ8
DDR_DQ9: U1.U21(DDR_DQ9) ; port DDR_BYTE0&1.DDR_DQ9
DDR_DQ10: U1.T22(DDR_DQ10) ; port DDR_BYTE0&1.DDR_DQ10
DDR_DQ11: U1.W21(DDR_DQ11) ; port DDR_BYTE0&1.DDR_DQ11
DDR_DQ12: U1.W23(DDR_DQ12) ; port DDR_BYTE0&1.DDR_DQ12
DDR_DQ13: U1.T23(DDR_DQ13) ; port DDR_BYTE0&1.DDR_DQ13
DDR_DQ14: U1.W22(DDR_DQ14) ; port DDR_BYTE0&1.DDR_DQ14
DDR_DQ15: U1.Y21(DDR_DQ15) ; port DDR_BYTE0&1.DDR_DQ15
DDR_DQ16: U1.B22(DDR_DQ16) ; port DDR_BYTE2&3.DDR_DQ16
DDR_DQ17: U1.D22(DDR_DQ17) ; port DDR_BYTE2&3.DDR_DQ17
DDR_DQ18: U1.D23(DDR_DQ18) ; port DDR_BYTE2&3.DDR_DQ18
DDR_DQ19: U1.B21(DDR_DQ19) ; port DDR_BYTE2&3.DDR_DQ19
DDR_DQ20: U1.A21(DDR_DQ20) ; port DDR_BYTE2&3.DDR_DQ20
DDR_DQ21: U1.E23(DDR_DQ21) ; port DDR_BYTE2&3.DDR_DQ21
DDR_DQ22: U1.D21(DDR_DQ22) ; port DDR_BYTE2&3.DDR_DQ22
DDR_DQ23: U1.A22(DDR_DQ23) ; port DDR_BYTE2&3.DDR_DQ23
DDR_DQ24: U1.Y23(DDR_DQ24) ; port DDR_BYTE2&3.DDR_DQ24
DDR_DQ25: U1.Y22(DDR_DQ25) ; port DDR_BYTE2&3.DDR_DQ25
DDR_DQ26: U1.AB21(DDR_DQ26) ; port DDR_BYTE2&3.DDR_DQ26
DDR_DQ27: U1.AB20(DDR_DQ27) ; port DDR_BYTE2&3.DDR_DQ27
DDR_DQ28: U1.AC22(DDR_DQ28) ; port DDR_BYTE2&3.DDR_DQ28
DDR_DQ29: U1.AC21(DDR_DQ29) ; port DDR_BYTE2&3.DDR_DQ29
DDR_DQ30: U1.AA23(DDR_DQ30) ; port DDR_BYTE2&3.DDR_DQ30
DDR_DQ31: U1.AA22(DDR_DQ31) ; port DDR_BYTE2&3.DDR_DQ31
DDR_DQM0: U1.H23(DDR_DQM0) ; port DDR_BYTE0&1.DDR_DQM0
DDR_DQM1: U1.V22(DDR_DQM1) ; port DDR_BYTE0&1.DDR_DQM1
DDR_DQM2: U1.C23(DDR_DQM2) ; port DDR_BYTE2&3.DDR_DQM2
DDR_DQM3: U1.AA20(DDR_DQM3) ; port DDR_BYTE2&3.DDR_DQM3
DDR_DQS0_N: U1.G23(DDR_DQS0N) ; port DDR_BYTE0&1.DDR_DQS0_N
DDR_DQS0_P: U1.G22(DDR_DQS0P) ; port DDR_BYTE0&1.DDR_DQS0_P
DDR_DQS1_N: U1.U23(DDR_DQS1N) ; port DDR_BYTE0&1.DDR_DQS1_N
DDR_DQS1_P: U1.U22(DDR_DQS1P) ; port DDR_BYTE0&1.DDR_DQS1_P
DDR_DQS2_N: U1.B23(DDR_DQS2N) ; port DDR_BYTE2&3.DDR_DQS2_N
DDR_DQS2_P: U1.C22(DDR_DQS2P) ; port DDR_BYTE2&3.DDR_DQS2_P
DDR_DQS3_N: U1.AB23(DDR_DQS3N) ; port DDR_BYTE2&3.DDR_DQS3_N
DDR_DQS3_P: U1.AB22(DDR_DQS3P) ; port DDR_BYTE2&3.DDR_DQS3_P
I2C4_SCL: R37.2 U1.Y18(PD12) ; port I2C4_SCL
I2C4_SDA: R38.2 U1.AA19(PD13) ; port I2C4_SDA
NRST: U1.M3(NRST) ; port NRST
PA0_WKUP: U1.AB3(PA0) ; port PA0_WKUP
PWR_ON: U1.R2(PWR_ON) ; port PWR_ON
SDMMC2_CK: U1.C9(PE3) ; port SDMMC2_CK
SDMMC2_CMD: U1.A10(PG6) ; port SDMMC2_CMD
SDMMC2_D0: U1.C13(PB14)
SDMMC2_D1: U1.B12(PB15)
SDMMC2_D2: U1.A11(PB3)
SDMMC2_D3: U1.B13(PB4)
SDMMC2_D4: U1.A13(PA8)
SDMMC2_D5: U1.B10(PB9)
SDMMC2_D6: U1.C11(PE5)
SDMMC2_D7: U1.B11(PC7)
NetR24_1: R24.1 U1.K23(DDR_ZQ)

Not connected (* = marked no-connect by the designer): U1 A2(PH5)* A3(PE13)* A4(PE11)* A5(PF1)* A7(PD5)* A8(PA9)* A14(PF2)* A16(DSI_CKN)* A17(DSI_D1N)* A19(JTDO-TRACESWO)* A20(JTDI)* AA1(PG14)* AA2(PG13)* AA3(PH3)* AA4(PA1)* AA6(PC1)* AA7(PB1)* AA9(PE9)* AA10(PB13)* AA11(PE7)* AA13(PF6)* AA14(PF9)* AA18(PA11)* AB1(PB11)* AB2(PG4)* AB4(PH2)* AB5(PC0)* AB6(PB0)* AB7(PC5)* AB8(PA7)* AB9(PG8)* AB10(PB8)* AB11(PG10)* AB12(PF7)* AB16(USB_DM2)* AB17(USB_DM1)* AB18(USB_RREF)* AB19(PA12)* AC2(PG0)* AC3(PA2)* AC4(PF14)* AC5(PB12)* AC7(PC4)* AC8(PA6)* AC10(PD11)* AC11(PF8)* AC13(PE8)* AC14(PG7)* AC16(USB_DP2)* AC17(USB_DP1)* AC19(OTG_VBUS)* B1(PH15)* B2(PH12)* B3(PH4)* B4(PE12)* B5(PD10)* B6(PD4)* B7(PG15)* B8(PD0)* B9(PD1)* B14(PC6)* B15(DSI_D0N)* B16(DSI_CKP)* B17(DSI_D1P)* B19(NJTRST)* B20(JTCK-SWCLK)* C1(PI0)* C2(PH10)* C3(PH14)* C4(PH11)* C5(PH9)* C6(PE14)* C8(PE1)* C10(PE6)* C15(DSI_D0P)* C19(PA15)* C20(JTMS-SWDIO)* D1(PH13)* D2(PD6)* D3(PE15)* D5(PH8)* D6(PE0)* D7(PF5)* D8(PF0)* D9(PF4)* D10(PD7)* D11(PB7)* D12(PD2)* D13(PC12)* D14(PD3)* D15(PC10)* D16(PC11)* D17(PC9)* D18(PC8)* D19(PE4)* D20(DDR_RESETN)* E1(PI3)* E2(PI2)* E3(PI1)* E4(PI4)* F2(PI7)* F3(PI5)* F4(PI6)* F20(DDR_A13)* G1(PZ1)* G2(PZ4)* G3(PZ0)* G4(PZ3)* H1(PZ6)* H2(PZ5)* H4(PI9)* J2(PD15)* J3(PZ7)* J4(PZ2)* K1(PD9)* K2(PC13)* K3(PD8)* K4(PG12)* K20(DDR_DTO0)* L1(PC15-OSC32_OUT)* L2(PC14-OSC32_IN)* L3(PD14)* L4(PI8)* L21(DDR_DTO1)* L22(DDR_ODT)* L23(DDR_BA0)* M2(BOOT2)* M4(NRST_CORE)* M20(DDR_WEN)* M21(DDR_BA2)* N1(BOOT0)* N2(PA13)* N3(PWR_LP)* N4(BOOT1)* N20(DDR_CASN)* N21(DDR_RASN)* P1(PH0-OSC_IN)* P2(PH1-OSC_OUT)* P4(PI11)* P20(DDR_A15)* P23(DDR_A12)* R3(PDR_ON)* R20(DDR_A11)* R21(DDR_A14)* R22(DDR_A10)* T1(PI10)* T2(PA14)* T3(PDR_ON_CORE)* T4(PG3)* U1(PF3)* U2(PA3)* U3(ANA0)* U4(ANA1)* U20(DDR_BA1)* V2(PG2)* V3(PA5)* V4(PA4)* W1(PG1)* W2(PC3)* W4(PH7)* Y1(PE2)* Y2(PC2)* Y3(PB10)* Y4(PF15)* Y5(PF13)* Y6(PG5)* Y7(PG11)* Y8(PB5)* Y9(PF12)* Y10(PF11)* Y11(PH6)* Y12(PF10)* Y13(PG9)* Y14(PB6)* Y15(PE10)* Y16(PB2)* Y17(PA10)* Y19(DDR_ATO)*

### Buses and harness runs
bus SDMMC2_D[0..7] = port SDMMC2_D[0..7]

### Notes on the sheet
- eMMC
- POWER - PMIC

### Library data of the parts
C17 = MCD-00006: as C78 on sheet eMMC
R24 = MCD-00120: Resistor,240R,0402,1%,1/16W; Manufacturer_Part_Number: RC0402FR-07240RL; Manufacturer: YAGEO; ECCN_US: EAR99; ECCN_EU: NEC; Provided_By: SUBCO
R37 R38 = MCD-00068: Resistor,1K5,0402,1%,1/16W; Manufacturer_Part_Number: RC0402FR-071K5L; Manufacturer: YAGEO; ECCN_US: EAR99; ECCN_EU: NEC; Provided_By: SUBCO
U1 = MCD-00677: as U1 on sheet Power_MPU

## Sheet 1LPDDR3_32bits.SchDoc: 1LPDDR3 32 Bits
size A3; CompanyName: STMicroelectronics; Address1: 12, Rue Jules HOROWITZ; Address2: 38019 Grenoble; Address3: FRANCE; DocumentNumber: .; SheetNumber: 7; SheetTotal: 7
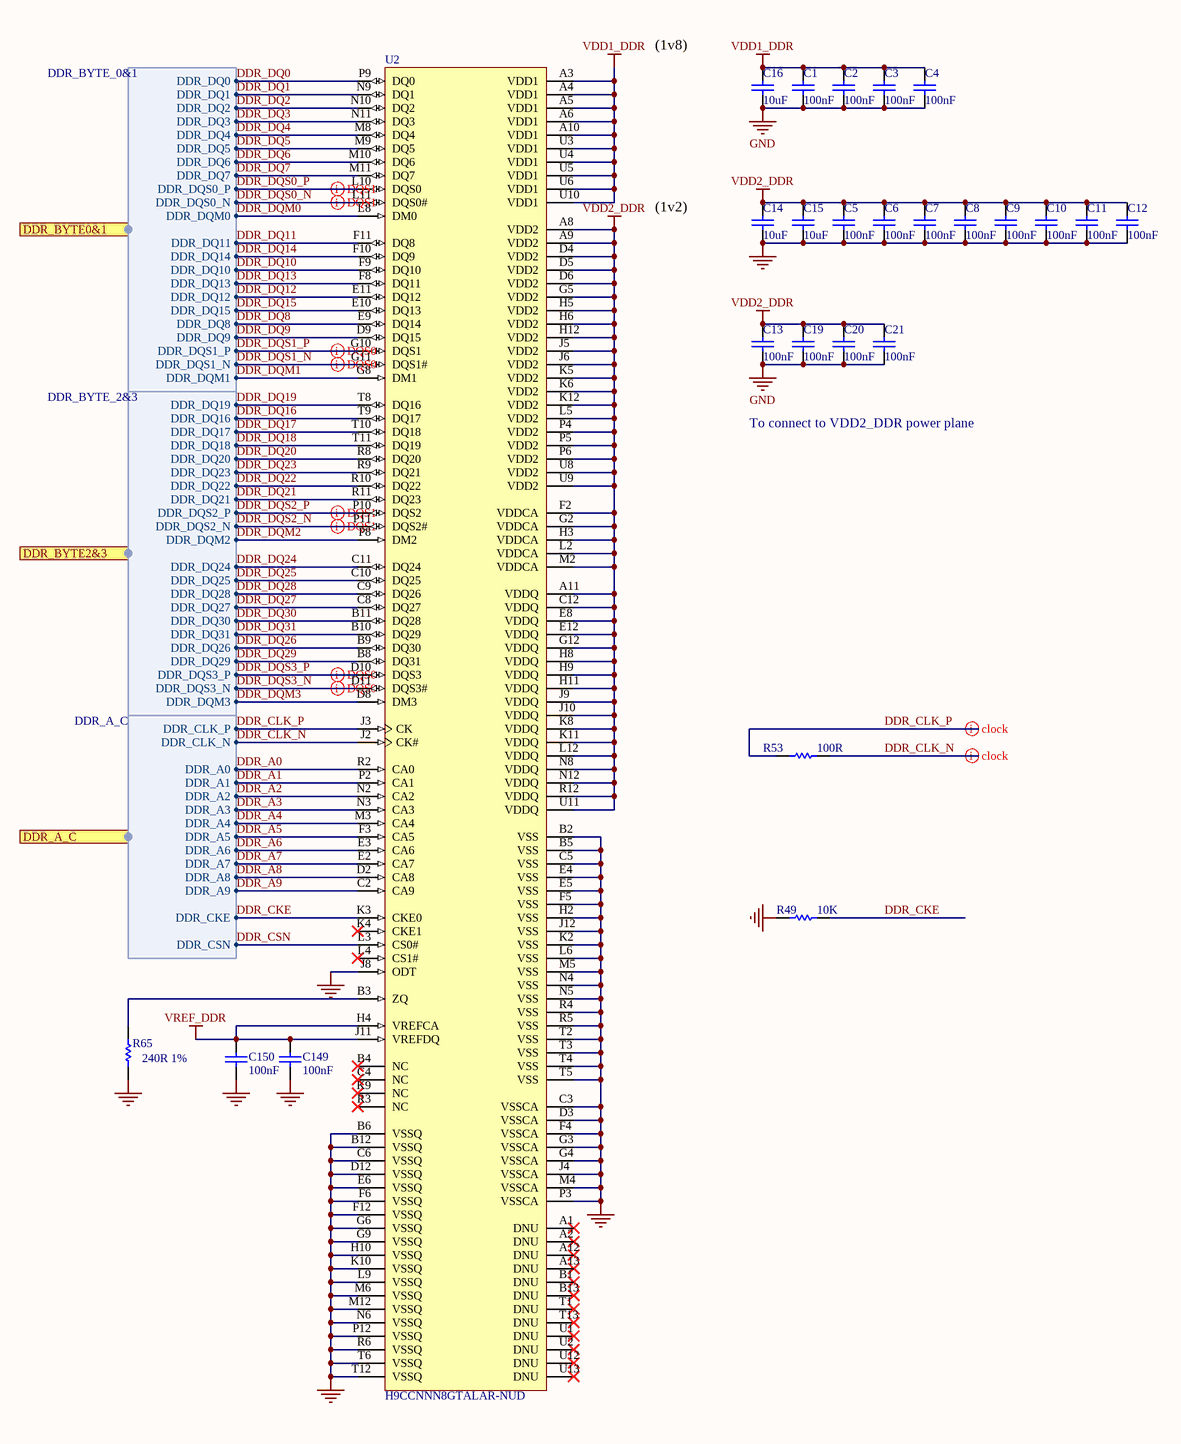
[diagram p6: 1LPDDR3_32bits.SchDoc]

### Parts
C1  value 100nF  [C0402]  (hidden comment: Capacitor)
C2  value 100nF  [C0402]  (hidden comment: Capacitor)
C3  value 100nF  [C0402]  (hidden comment: Capacitor)
C4  value 100nF  [C0402]  (hidden comment: Capacitor)
C5  value 100nF  [C0402]  (hidden comment: Capacitor)
C6  value 100nF  [C0402]  (hidden comment: Capacitor)
C7  value 100nF  [C0402]  (hidden comment: Capacitor)
C8  value 100nF  [C0402]  (hidden comment: Capacitor)
C9  value 100nF  [C0402]  (hidden comment: Capacitor)
C10  value 100nF  [C0402]  (hidden comment: Capacitor)
C11  value 100nF  [C0402]  (hidden comment: Capacitor)
C12  value 100nF  [C0402]  (hidden comment: Capacitor)
C13  value 100nF  [C0402]  (hidden comment: Capacitor)
C14  value 10uF  [C0603]  (hidden comment: Capacitor)
C15  value 10uF  [C0603]  (hidden comment: Capacitor)
C16  value 10uF  [C0603]  (hidden comment: Capacitor)
C19  value 100nF  [C0402]  (hidden comment: Capacitor)
C20  value 100nF  [C0402]  (hidden comment: Capacitor)
C21  value 100nF  [C0402]  (hidden comment: Capacitor)
C149  value 100nF  [C0402]  (hidden comment: Capacitor)
C150  value 100nF  [C0402]  (hidden comment: Capacitor)
R49  value 10K  [R0402]  (hidden comment: Resistor)
R53  value 100R  [R0402]  (hidden comment: Resistor)
R65  value 240R 1%  [R0402]  (hidden comment: Resistor)
U2  H9CCNNN8GTALAR-NUD  [ICC_FBGA178_11X11P5_P080-065]

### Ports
DDR_A_C (harness DDR_A_C), DDR_BYTE0&1 (harness DDR_BYTE_0&1), DDR_BYTE2&3 (harness DDR_BYTE_2&3)

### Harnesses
DDR_A_C: DDR_A4, DDR_A0, DDR_A2, DDR_A1, DDR_A6, DDR_A3, DDR_A5, DDR_A7, DDR_A8, DDR_A9, DDR_CKE, DDR_CSN, DDR_CLK_P, DDR_CLK_N
DDR_BYTE_2&3: DDR_DQ18, DDR_DQ19, DDR_DQ17, DDR_DQ16, DDR_DQ23, DDR_DQ21, DDR_DQ20, DDR_DQ22, DDR_DQS2_P, DDR_DQS2_N, DDR_DQ28, DDR_DQM2, DDR_DQ24, DDR_DQ30, DDR_DQ25, DDR_DQ27, DDR_DQ31, DDR_DQ26, DDR_DQ29, DDR_DQS3_P, DDR_DQS3_N, DDR_DQM3
DDR_BYTE_0&1: DDR_DQ0, DDR_DQ1, DDR_DQ2, DDR_DQ3, DDR_DQ4, DDR_DQ5, DDR_DQ6, DDR_DQ7, DDR_DQS0_P, DDR_DQS0_N, DDR_DQM1, DDR_DQ11, DDR_DQ14, DDR_DQ12, DDR_DQ13, DDR_DQ10, DDR_DQ15, DDR_DQ8, DDR_DQ9, DDR_DQS1_P, DDR_DQS1_N, DDR_DQM0

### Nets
GND: C1.2 C2.2 C3.2 C4.2 C5.2 C6.2 C7.2 C8.2 C9.2 C10.2 C11.2 C12.2 C13.2 C14.1 C15.1 C16.1 C19.2 C20.2 C21.2 C149.2 C150.2 R49.1 R65.2 U2.B2(VSS) U2.B5(VSS) U2.B6(VSSQ) U2.B12(VSSQ) U2.C3(VSSCA) U2.C5(VSS) U2.C6(VSSQ) U2.D3(VSSCA) U2.D12(VSSQ) U2.E4(VSS) U2.E5(VSS) U2.E6(VSSQ) U2.F4(VSSCA) U2.F5(VSS) U2.F6(VSSQ) U2.F12(VSSQ) U2.G3(VSSCA) U2.G4(VSSCA) U2.G6(VSSQ) U2.G9(VSSQ) U2.H2(VSS) U2.H10(VSSQ) U2.J4(VSSCA) U2.J8(ODT) U2.J12(VSS) U2.K2(VSS) U2.K10(VSSQ) U2.L6(VSS) U2.L9(VSSQ) U2.M4(VSSCA) U2.M5(VSS) U2.M6(VSSQ) U2.M12(VSSQ) U2.N4(VSS) U2.N5(VSS) U2.N6(VSSQ) U2.P3(VSSCA) U2.P12(VSSQ) U2.R4(VSS) U2.R5(VSS) U2.R6(VSSQ) U2.T2(VSS) U2.T3(VSS) U2.T4(VSS) U2.T5(VSS) U2.T6(VSSQ) U2.T12(VSSQ)
VDD1_DDR: C1.1 C2.1 C3.1 C4.1 C16.2 U2.A3(VDD1) U2.A4(VDD1) U2.A5(VDD1) U2.A6(VDD1) U2.A10(VDD1) U2.U3(VDD1) U2.U4(VDD1) U2.U5(VDD1) U2.U6(VDD1) U2.U10(VDD1)
VDD2_DDR: C5.1 C6.1 C7.1 C8.1 C9.1 C10.1 C11.1 C12.1 C13.1 C14.2 C15.2 C19.1 C20.1 C21.1 U2.A8(VDD2) U2.A9(VDD2) U2.A11(VDDQ) U2.C12(VDDQ) U2.D4(VDD2) U2.D5(VDD2) U2.D6(VDD2) U2.E8(VDDQ) U2.E12(VDDQ) U2.F2(VDDCA) U2.G2(VDDCA) U2.G5(VDD2) U2.G12(VDDQ) U2.H3(VDDCA) U2.H5(VDD2) U2.H6(VDD2) U2.H8(VDDQ) U2.H9(VDDQ) U2.H11(VDDQ) U2.H12(VDD2) U2.J5(VDD2) U2.J6(VDD2) U2.J9(VDDQ) U2.J10(VDDQ) U2.K5(VDD2) U2.K6(VDD2) U2.K8(VDDQ) U2.K11(VDDQ) U2.K12(VDD2) U2.L2(VDDCA) U2.L5(VDD2) U2.L12(VDDQ) U2.M2(VDDCA) U2.N8(VDDQ) U2.N12(VDDQ) U2.P4(VDD2) U2.P5(VDD2) U2.P6(VDD2) U2.R12(VDDQ) U2.U8(VDD2) U2.U9(VDD2) U2.U11(VDDQ)
VREF_DDR: C149.1 C150.1 U2.H4(VREFCA) U2.J11(VREFDQ)
DDR_A0: U2.R2(CA0) ; port DDR_A_C.DDR_A0
DDR_A1: U2.P2(CA1) ; port DDR_A_C.DDR_A1
DDR_A2: U2.N2(CA2) ; port DDR_A_C.DDR_A2
DDR_A3: U2.N3(CA3) ; port DDR_A_C.DDR_A3
DDR_A4: U2.M3(CA4) ; port DDR_A_C.DDR_A4
DDR_A5: U2.F3(CA5) ; port DDR_A_C.DDR_A5
DDR_A6: U2.E3(CA6) ; port DDR_A_C.DDR_A6
DDR_A7: U2.E2(CA7) ; port DDR_A_C.DDR_A7
DDR_A8: U2.D2(CA8) ; port DDR_A_C.DDR_A8
DDR_A9: U2.C2(CA9) ; port DDR_A_C.DDR_A9
DDR_CKE: R49.2 U2.K3(CKE0) ; port DDR_A_C.DDR_CKE
DDR_CLK_N: R53.2 U2.J2(CK#) ; port DDR_A_C.DDR_CLK_N
DDR_CLK_P: R53.1 U2.J3(CK) ; port DDR_A_C.DDR_CLK_P
DDR_CSN: U2.L3(CS0#) ; port DDR_A_C.DDR_CSN
DDR_DQ0: U2.P9(DQ0) ; port DDR_BYTE0&1.DDR_DQ0
DDR_DQ1: U2.N9(DQ1) ; port DDR_BYTE0&1.DDR_DQ1
DDR_DQ2: U2.N10(DQ2) ; port DDR_BYTE0&1.DDR_DQ2
DDR_DQ3: U2.N11(DQ3) ; port DDR_BYTE0&1.DDR_DQ3
DDR_DQ4: U2.M8(DQ4) ; port DDR_BYTE0&1.DDR_DQ4
DDR_DQ5: U2.M9(DQ5) ; port DDR_BYTE0&1.DDR_DQ5
DDR_DQ6: U2.M10(DQ6) ; port DDR_BYTE0&1.DDR_DQ6
DDR_DQ7: U2.M11(DQ7) ; port DDR_BYTE0&1.DDR_DQ7
DDR_DQ8: U2.E9(DQ14) ; port DDR_BYTE0&1.DDR_DQ8
DDR_DQ9: U2.D9(DQ15) ; port DDR_BYTE0&1.DDR_DQ9
DDR_DQ10: U2.F9(DQ10) ; port DDR_BYTE0&1.DDR_DQ10
DDR_DQ11: U2.F11(DQ8) ; port DDR_BYTE0&1.DDR_DQ11
DDR_DQ12: U2.E11(DQ12) ; port DDR_BYTE0&1.DDR_DQ12
DDR_DQ13: U2.F8(DQ11) ; port DDR_BYTE0&1.DDR_DQ13
DDR_DQ14: U2.F10(DQ9) ; port DDR_BYTE0&1.DDR_DQ14
DDR_DQ15: U2.E10(DQ13) ; port DDR_BYTE0&1.DDR_DQ15
DDR_DQ16: U2.T9(DQ17) ; port DDR_BYTE2&3.DDR_DQ16
DDR_DQ17: U2.T10(DQ18) ; port DDR_BYTE2&3.DDR_DQ17
DDR_DQ18: U2.T11(DQ19) ; port DDR_BYTE2&3.DDR_DQ18
DDR_DQ19: U2.T8(DQ16) ; port DDR_BYTE2&3.DDR_DQ19
DDR_DQ20: U2.R8(DQ20) ; port DDR_BYTE2&3.DDR_DQ20
DDR_DQ21: U2.R11(DQ23) ; port DDR_BYTE2&3.DDR_DQ21
DDR_DQ22: U2.R10(DQ22) ; port DDR_BYTE2&3.DDR_DQ22
DDR_DQ23: U2.R9(DQ21) ; port DDR_BYTE2&3.DDR_DQ23
DDR_DQ24: U2.C11(DQ24) ; port DDR_BYTE2&3.DDR_DQ24
DDR_DQ25: U2.C10(DQ25) ; port DDR_BYTE2&3.DDR_DQ25
DDR_DQ26: U2.B9(DQ30) ; port DDR_BYTE2&3.DDR_DQ26
DDR_DQ27: U2.C8(DQ27) ; port DDR_BYTE2&3.DDR_DQ27
DDR_DQ28: U2.C9(DQ26) ; port DDR_BYTE2&3.DDR_DQ28
DDR_DQ29: U2.B8(DQ31) ; port DDR_BYTE2&3.DDR_DQ29
DDR_DQ30: U2.B11(DQ28) ; port DDR_BYTE2&3.DDR_DQ30
DDR_DQ31: U2.B10(DQ29) ; port DDR_BYTE2&3.DDR_DQ31
DDR_DQM0: U2.L8(DM0) ; port DDR_BYTE0&1.DDR_DQM0
DDR_DQM1: U2.G8(DM1) ; port DDR_BYTE0&1.DDR_DQM1
DDR_DQM2: U2.P8(DM2) ; port DDR_BYTE2&3.DDR_DQM2
DDR_DQM3: U2.D8(DM3) ; port DDR_BYTE2&3.DDR_DQM3
DDR_DQS0_N: U2.L11(DQS0#) ; port DDR_BYTE0&1.DDR_DQS0_N
DDR_DQS0_P: U2.L10(DQS0) ; port DDR_BYTE0&1.DDR_DQS0_P
DDR_DQS1_N: U2.G11(DQS1#) ; port DDR_BYTE0&1.DDR_DQS1_N
DDR_DQS1_P: U2.G10(DQS1) ; port DDR_BYTE0&1.DDR_DQS1_P
DDR_DQS2_N: U2.P11(DQS2#) ; port DDR_BYTE2&3.DDR_DQS2_N
DDR_DQS2_P: U2.P10(DQS2) ; port DDR_BYTE2&3.DDR_DQS2_P
DDR_DQS3_N: U2.D11(DQS3#) ; port DDR_BYTE2&3.DDR_DQS3_N
DDR_DQS3_P: U2.D10(DQS3) ; port DDR_BYTE2&3.DDR_DQS3_P
NetR65_1: R65.1 U2.B3(ZQ)

Not connected (* = marked no-connect by the designer): U2 A1(DNU)* A2(DNU)* A12(DNU)* A13(DNU)* B1(DNU)* B4(NC)* B13(DNU)* C4(NC)* K4(CKE1)* K9(NC)* L4(CS1#)* R3(NC)* T1(DNU)* T13(DNU)* U1(DNU)* U2(DNU)* U12(DNU)* U13(DNU)*

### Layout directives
differential pair: DDR_CLK_N, DDR_CLK_P, DDR_DQS0_N, DDR_DQS0_P, DDR_DQS1_N, DDR_DQS1_P, DDR_DQS2_N, DDR_DQS2_P, DDR_DQS3_N, DDR_DQS3_P

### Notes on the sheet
- (1v8)
- (1v2)
- To connect to VDD2_DDR power plane

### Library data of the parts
C1-C13 C19-C21 C149 C150 = MCD-00006: as C61 on sheet Power_MPU
C14-C16 = MCD-01124: Capacitor, MLCC, 10uF, 10V, X5R, +/-10%, 0603, T=0.8mm; Manufacturer_Part_Number: GRM188R61A106KAAL; Manufacturer: MURATA; Provided_By: SUBCO; ECCN_US: EAR99; ECCN_EU: NEC; Order_Code_RS: 170-6258
R49 = MCD-00053: Resistor,10K,0402,1%,1/16W; Manufacturer_Part_Number: RC0402FR-0710KL; Manufacturer: YAGEO; BMS_Part_Number: 9131590; ECCN_US: EAR99; ECCN_EU: NEC; Provided_By: SUBCO
R53 = MCD-00067: Resistor,100R,0402,1%,1/16W; Manufacturer_Part_Number: RC0402FR-07100RL; Manufacturer: YAGEO; ECCN_US: EAR99; ECCN_EU: NEC; Provided_By: SUBCO
R65 = MCD-00120: Resistor,240R,0402,1%,1/16W; Manufacturer_Part_Number: RC0402FR-07240RL; Manufacturer: YAGEO; Provided_By: SUBCO; ECCN_US: EAR99; ECCN_EU: NEC
U2 = MCD-00209: Memory,LPDDR3,8Gb,256Mbx32,1866MT/s,1V8,FBGA178; Part_Type: IC; Manufacturer: SKHYNIX; Provided_By: SUBCO

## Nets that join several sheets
3V3: Power_PMIC (5 pins), eMMC (6 pins)
GND: Power_PMIC (28 pins), Power_MPU (87 pins), eMMC (17 pins), STM32_MPU_IOs (C17.2 R24.2 U1.AB13), 1LPDDR3_32bits (70 pins)
VDD: Power_PMIC (6 pins), Power_MPU (15 pins), eMMC (8 pins), STM32_MPU_IOs (R37.1 R38.1)
VDD1_DDR: Power_PMIC (C46.2 U4.14), 1LPDDR3_32bits (15 pins)
VDD2_DDR: Power_PMIC (C29.2 L2.2 U4.9), Power_MPU (17 pins), 1LPDDR3_32bits (56 pins)
VDD_CORE: Power_PMIC (C34.2 L1.2 U4.5), Power_MPU (27 pins)
VDD_USB: Power_PMIC (C52.2 U4.39), Power_MPU (C71.2 U1.AA15 U1.AA17)
VDDA: Power_PMIC (C49.2 U4.20), Power_MPU (C70.2 R41.1 U1.1H1)
VREF_DDR: Power_PMIC (C84.2 U4.16), STM32_MPU_IOs (C17.1 U1.AC20), 1LPDDR3_32bits (C149.1 C150.1 U2.H4 U2.J11)
DDR_A0: STM32_MPU_IOs (U1.L20), 1LPDDR3_32bits (U2.R2)
DDR_A1: STM32_MPU_IOs (U1.P22), 1LPDDR3_32bits (U2.P2)
DDR_A2: STM32_MPU_IOs (U1.J20), 1LPDDR3_32bits (U2.N2)
DDR_A3: STM32_MPU_IOs (U1.K22), 1LPDDR3_32bits (U2.N3)
DDR_A4: STM32_MPU_IOs (U1.V20), 1LPDDR3_32bits (U2.M3)
DDR_A5: STM32_MPU_IOs (U1.H20), 1LPDDR3_32bits (U2.F3)
DDR_A6: STM32_MPU_IOs (U1.W20), 1LPDDR3_32bits (U2.E3)
DDR_A7: STM32_MPU_IOs (U1.E20), 1LPDDR3_32bits (U2.E2)
DDR_A8: STM32_MPU_IOs (U1.Y20), 1LPDDR3_32bits (U2.D2)
DDR_A9: STM32_MPU_IOs (U1.G20), 1LPDDR3_32bits (U2.C2)
DDR_CKE: STM32_MPU_IOs (U1.T20), 1LPDDR3_32bits (R49.2 U2.K3)
DDR_CLK_N: STM32_MPU_IOs (U1.N23), 1LPDDR3_32bits (R53.2 U2.J2)
DDR_CLK_P: STM32_MPU_IOs (U1.N22), 1LPDDR3_32bits (R53.1 U2.J3)
DDR_CSN: STM32_MPU_IOs (U1.M22), 1LPDDR3_32bits (U2.L3)
DDR_DQ0: STM32_MPU_IOs (U1.E22), 1LPDDR3_32bits (U2.P9)
DDR_DQ1: STM32_MPU_IOs (U1.F22), 1LPDDR3_32bits (U2.N9)
DDR_DQ2: STM32_MPU_IOs (U1.H21), 1LPDDR3_32bits (U2.N10)
DDR_DQ3: STM32_MPU_IOs (U1.E21), 1LPDDR3_32bits (U2.N11)
DDR_DQ4: STM32_MPU_IOs (U1.J21), 1LPDDR3_32bits (U2.M8)
DDR_DQ5: STM32_MPU_IOs (U1.J22), 1LPDDR3_32bits (U2.M9)
DDR_DQ6: STM32_MPU_IOs (U1.H22), 1LPDDR3_32bits (U2.M10)
DDR_DQ7: STM32_MPU_IOs (U1.G21), 1LPDDR3_32bits (U2.M11)
DDR_DQ8: STM32_MPU_IOs (U1.T21), 1LPDDR3_32bits (U2.E9)
DDR_DQ9: STM32_MPU_IOs (U1.U21), 1LPDDR3_32bits (U2.D9)
DDR_DQ10: STM32_MPU_IOs (U1.T22), 1LPDDR3_32bits (U2.F9)
DDR_DQ11: STM32_MPU_IOs (U1.W21), 1LPDDR3_32bits (U2.F11)
DDR_DQ12: STM32_MPU_IOs (U1.W23), 1LPDDR3_32bits (U2.E11)
DDR_DQ13: STM32_MPU_IOs (U1.T23), 1LPDDR3_32bits (U2.F8)
DDR_DQ14: STM32_MPU_IOs (U1.W22), 1LPDDR3_32bits (U2.F10)
DDR_DQ15: STM32_MPU_IOs (U1.Y21), 1LPDDR3_32bits (U2.E10)
DDR_DQ16: STM32_MPU_IOs (U1.B22), 1LPDDR3_32bits (U2.T9)
DDR_DQ17: STM32_MPU_IOs (U1.D22), 1LPDDR3_32bits (U2.T10)
DDR_DQ18: STM32_MPU_IOs (U1.D23), 1LPDDR3_32bits (U2.T11)
DDR_DQ19: STM32_MPU_IOs (U1.B21), 1LPDDR3_32bits (U2.T8)
DDR_DQ20: STM32_MPU_IOs (U1.A21), 1LPDDR3_32bits (U2.R8)
DDR_DQ21: STM32_MPU_IOs (U1.E23), 1LPDDR3_32bits (U2.R11)
DDR_DQ22: STM32_MPU_IOs (U1.D21), 1LPDDR3_32bits (U2.R10)
DDR_DQ23: STM32_MPU_IOs (U1.A22), 1LPDDR3_32bits (U2.R9)
DDR_DQ24: STM32_MPU_IOs (U1.Y23), 1LPDDR3_32bits (U2.C11)
DDR_DQ25: STM32_MPU_IOs (U1.Y22), 1LPDDR3_32bits (U2.C10)
DDR_DQ26: STM32_MPU_IOs (U1.AB21), 1LPDDR3_32bits (U2.B9)
DDR_DQ27: STM32_MPU_IOs (U1.AB20), 1LPDDR3_32bits (U2.C8)
DDR_DQ28: STM32_MPU_IOs (U1.AC22), 1LPDDR3_32bits (U2.C9)
DDR_DQ29: STM32_MPU_IOs (U1.AC21), 1LPDDR3_32bits (U2.B8)
DDR_DQ30: STM32_MPU_IOs (U1.AA23), 1LPDDR3_32bits (U2.B11)
DDR_DQ31: STM32_MPU_IOs (U1.AA22), 1LPDDR3_32bits (U2.B10)
DDR_DQM0: STM32_MPU_IOs (U1.H23), 1LPDDR3_32bits (U2.L8)
DDR_DQM1: STM32_MPU_IOs (U1.V22), 1LPDDR3_32bits (U2.G8)
DDR_DQM2: STM32_MPU_IOs (U1.C23), 1LPDDR3_32bits (U2.P8)
DDR_DQM3: STM32_MPU_IOs (U1.AA20), 1LPDDR3_32bits (U2.D8)
DDR_DQS0_N: STM32_MPU_IOs (U1.G23), 1LPDDR3_32bits (U2.L11)
DDR_DQS0_P: STM32_MPU_IOs (U1.G22), 1LPDDR3_32bits (U2.L10)
DDR_DQS1_N: STM32_MPU_IOs (U1.U23), 1LPDDR3_32bits (U2.G11)
DDR_DQS1_P: STM32_MPU_IOs (U1.U22), 1LPDDR3_32bits (U2.G10)
DDR_DQS2_N: STM32_MPU_IOs (U1.B23), 1LPDDR3_32bits (U2.P11)
DDR_DQS2_P: STM32_MPU_IOs (U1.C22), 1LPDDR3_32bits (U2.P10)
DDR_DQS3_N: STM32_MPU_IOs (U1.AB23), 1LPDDR3_32bits (U2.D11)
DDR_DQS3_P: STM32_MPU_IOs (U1.AB22), 1LPDDR3_32bits (U2.D10)
I2C4_SCL: Power_PMIC (U4.4), STM32_MPU_IOs (R37.2 U1.Y18)
I2C4_SDA: Power_PMIC (U4.3), STM32_MPU_IOs (R38.2 U1.AA19)
NRST: Power_PMIC (U4.1), STM32_MPU_IOs (U1.M3)
PA0_WKUP: Power_PMIC (U4.43), STM32_MPU_IOs (U1.AB3)
PWR_ON: Power_PMIC (U4.44), STM32_MPU_IOs (U1.R2)

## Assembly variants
Example: all parts fitted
